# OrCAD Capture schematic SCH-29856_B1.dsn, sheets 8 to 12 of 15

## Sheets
8 08 AUDIO: size C
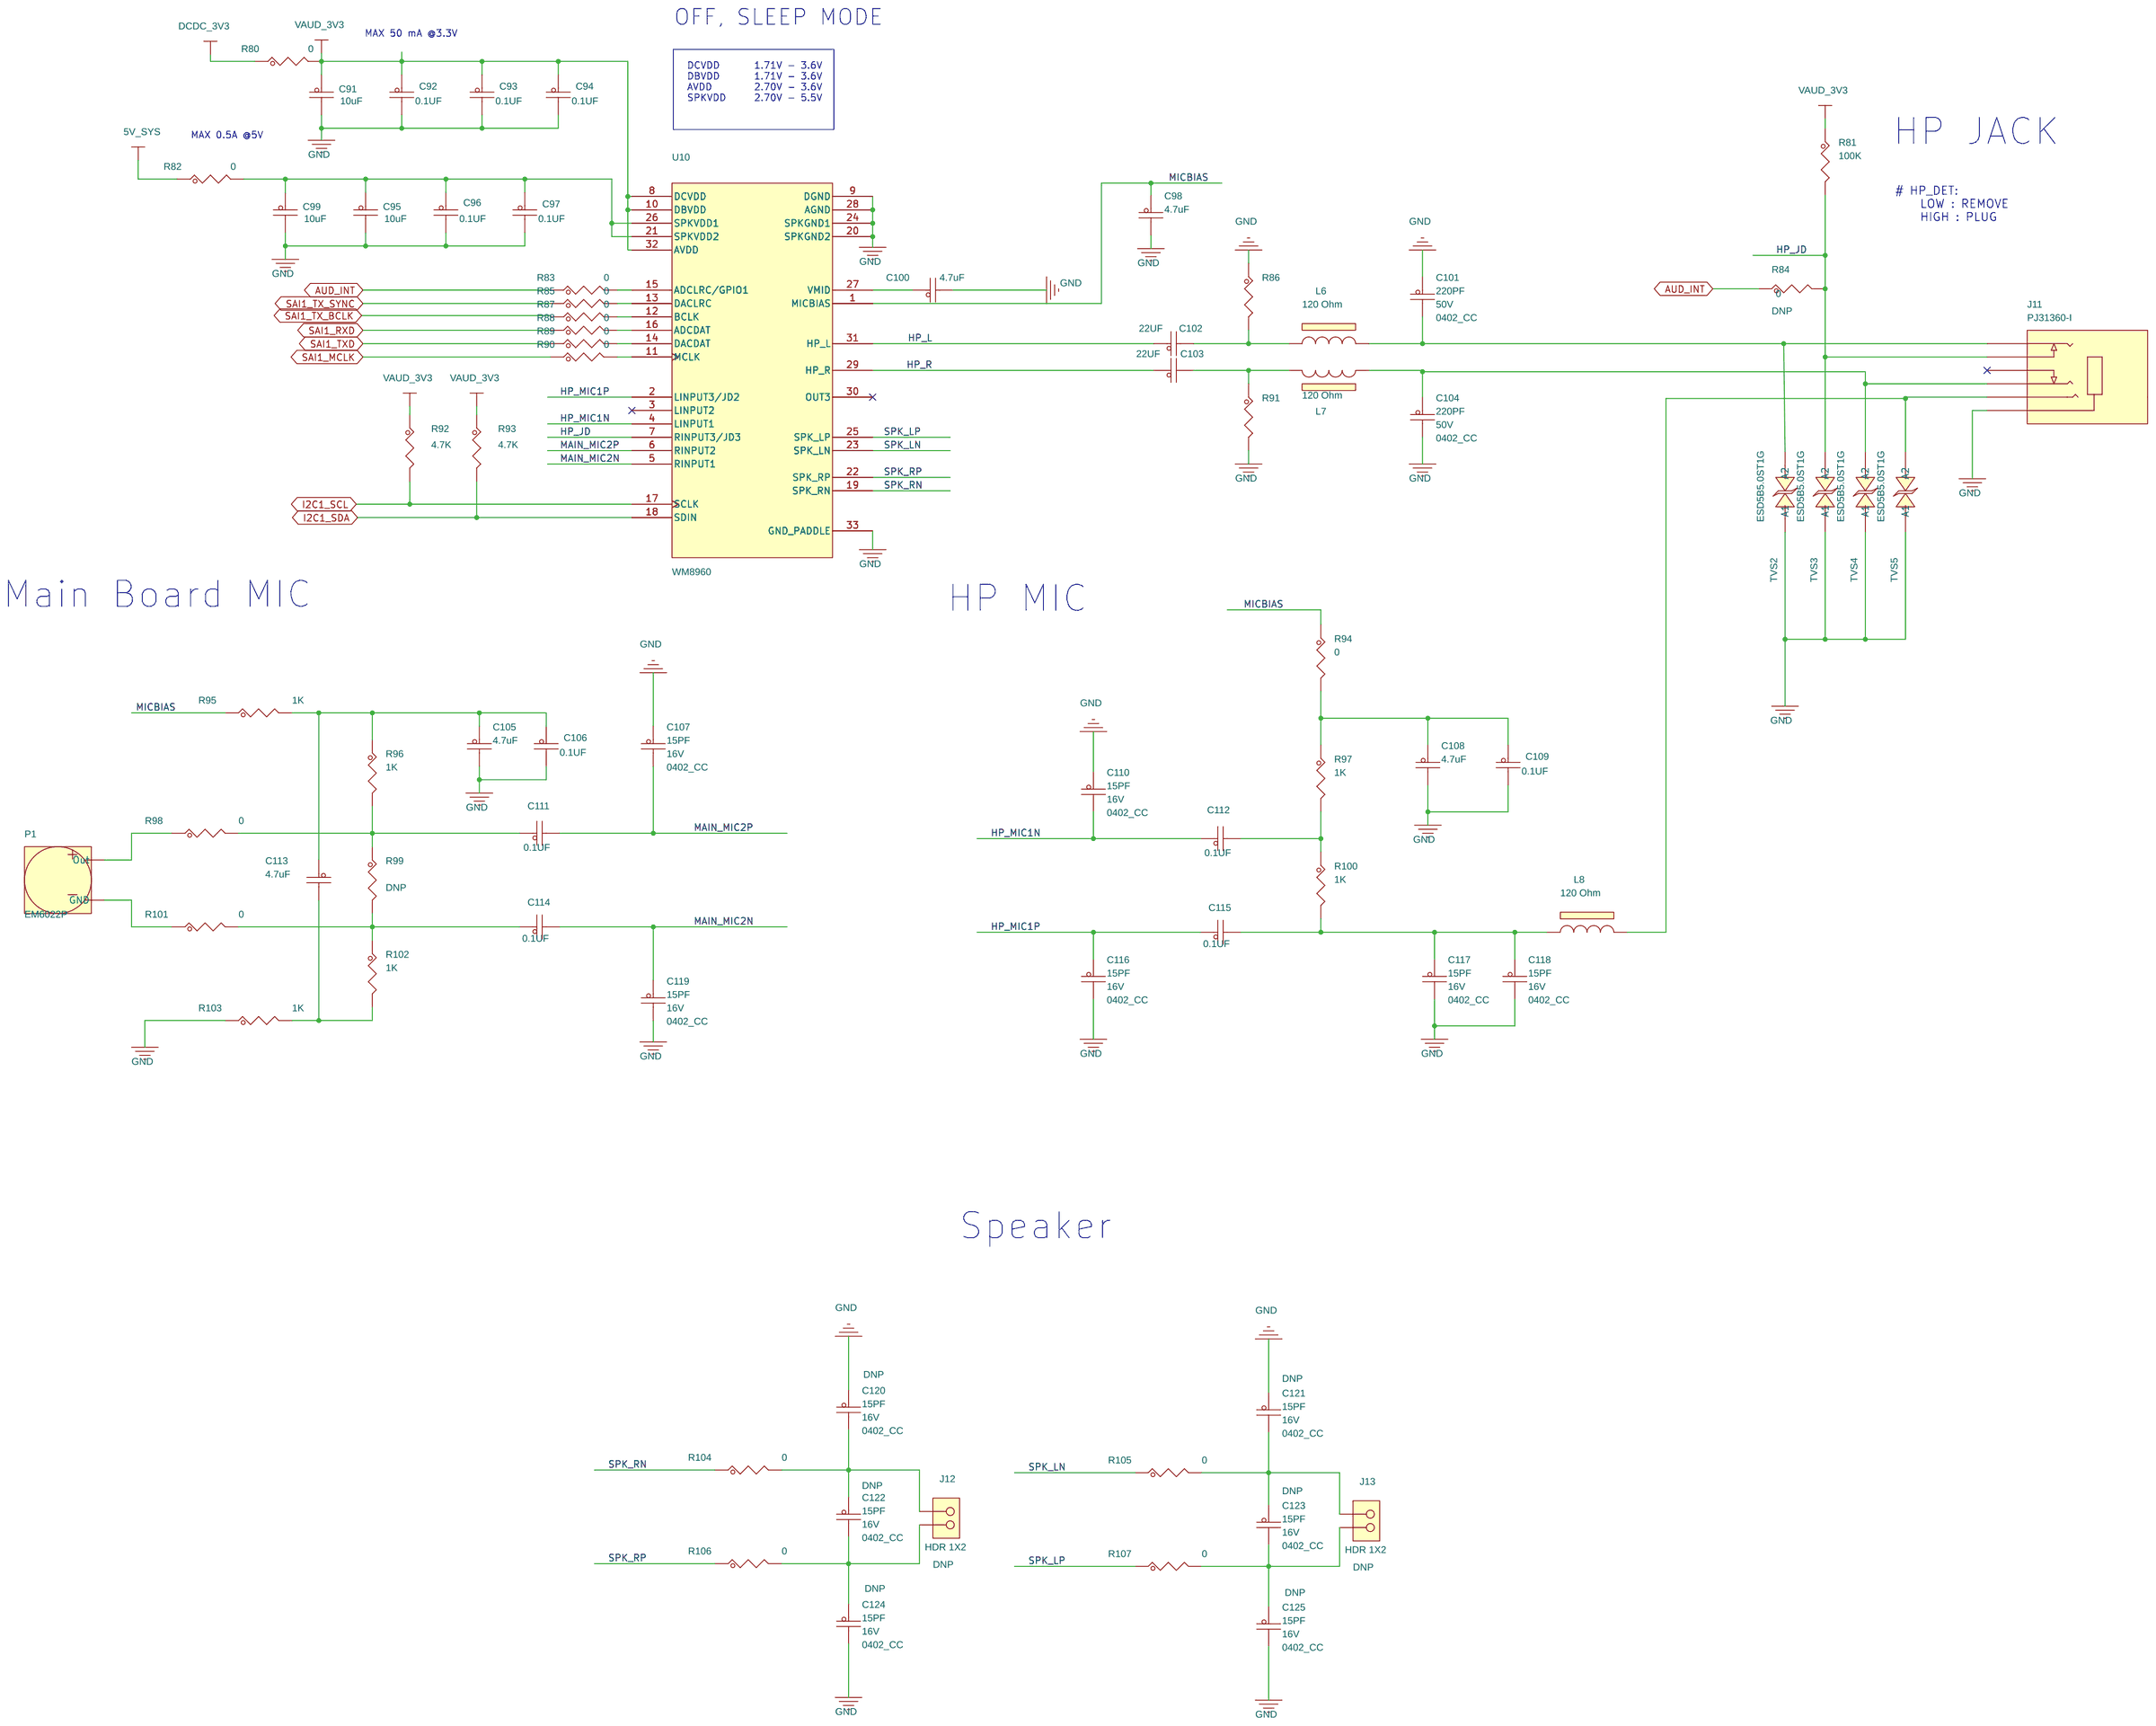
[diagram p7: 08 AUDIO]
9 09 ETHERNET: size C
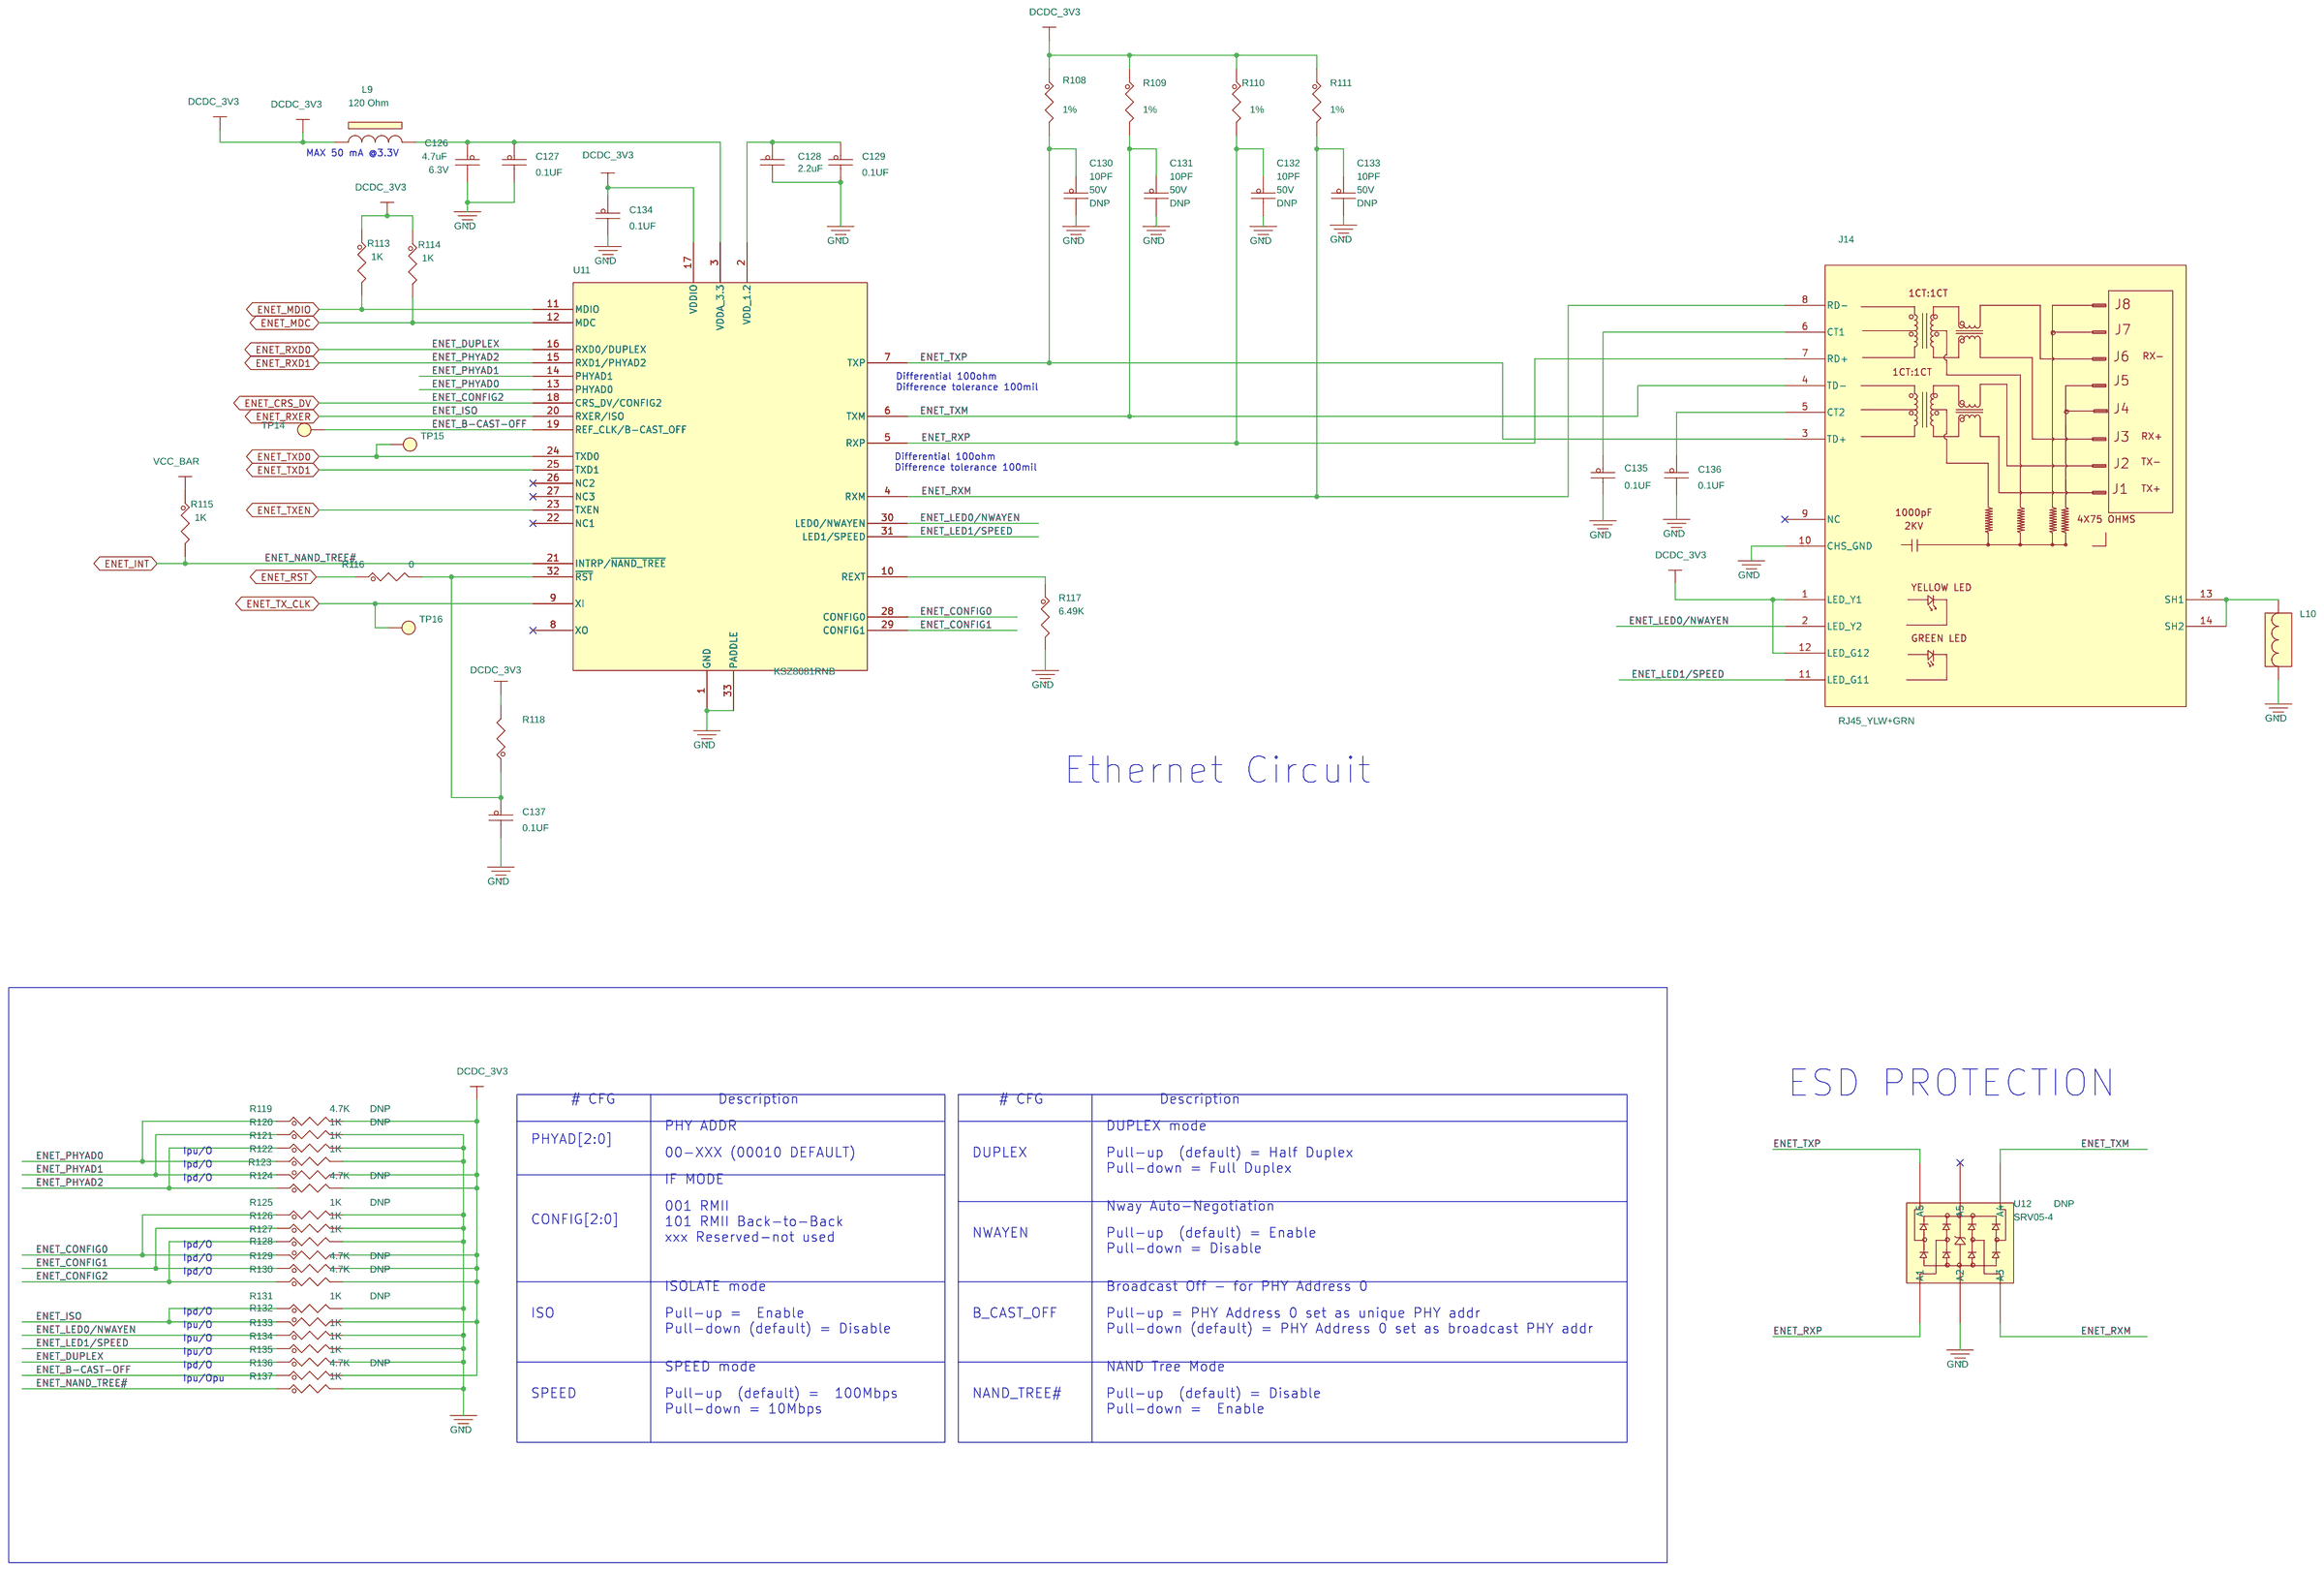
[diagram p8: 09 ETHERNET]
10 12 SDRAM: size C
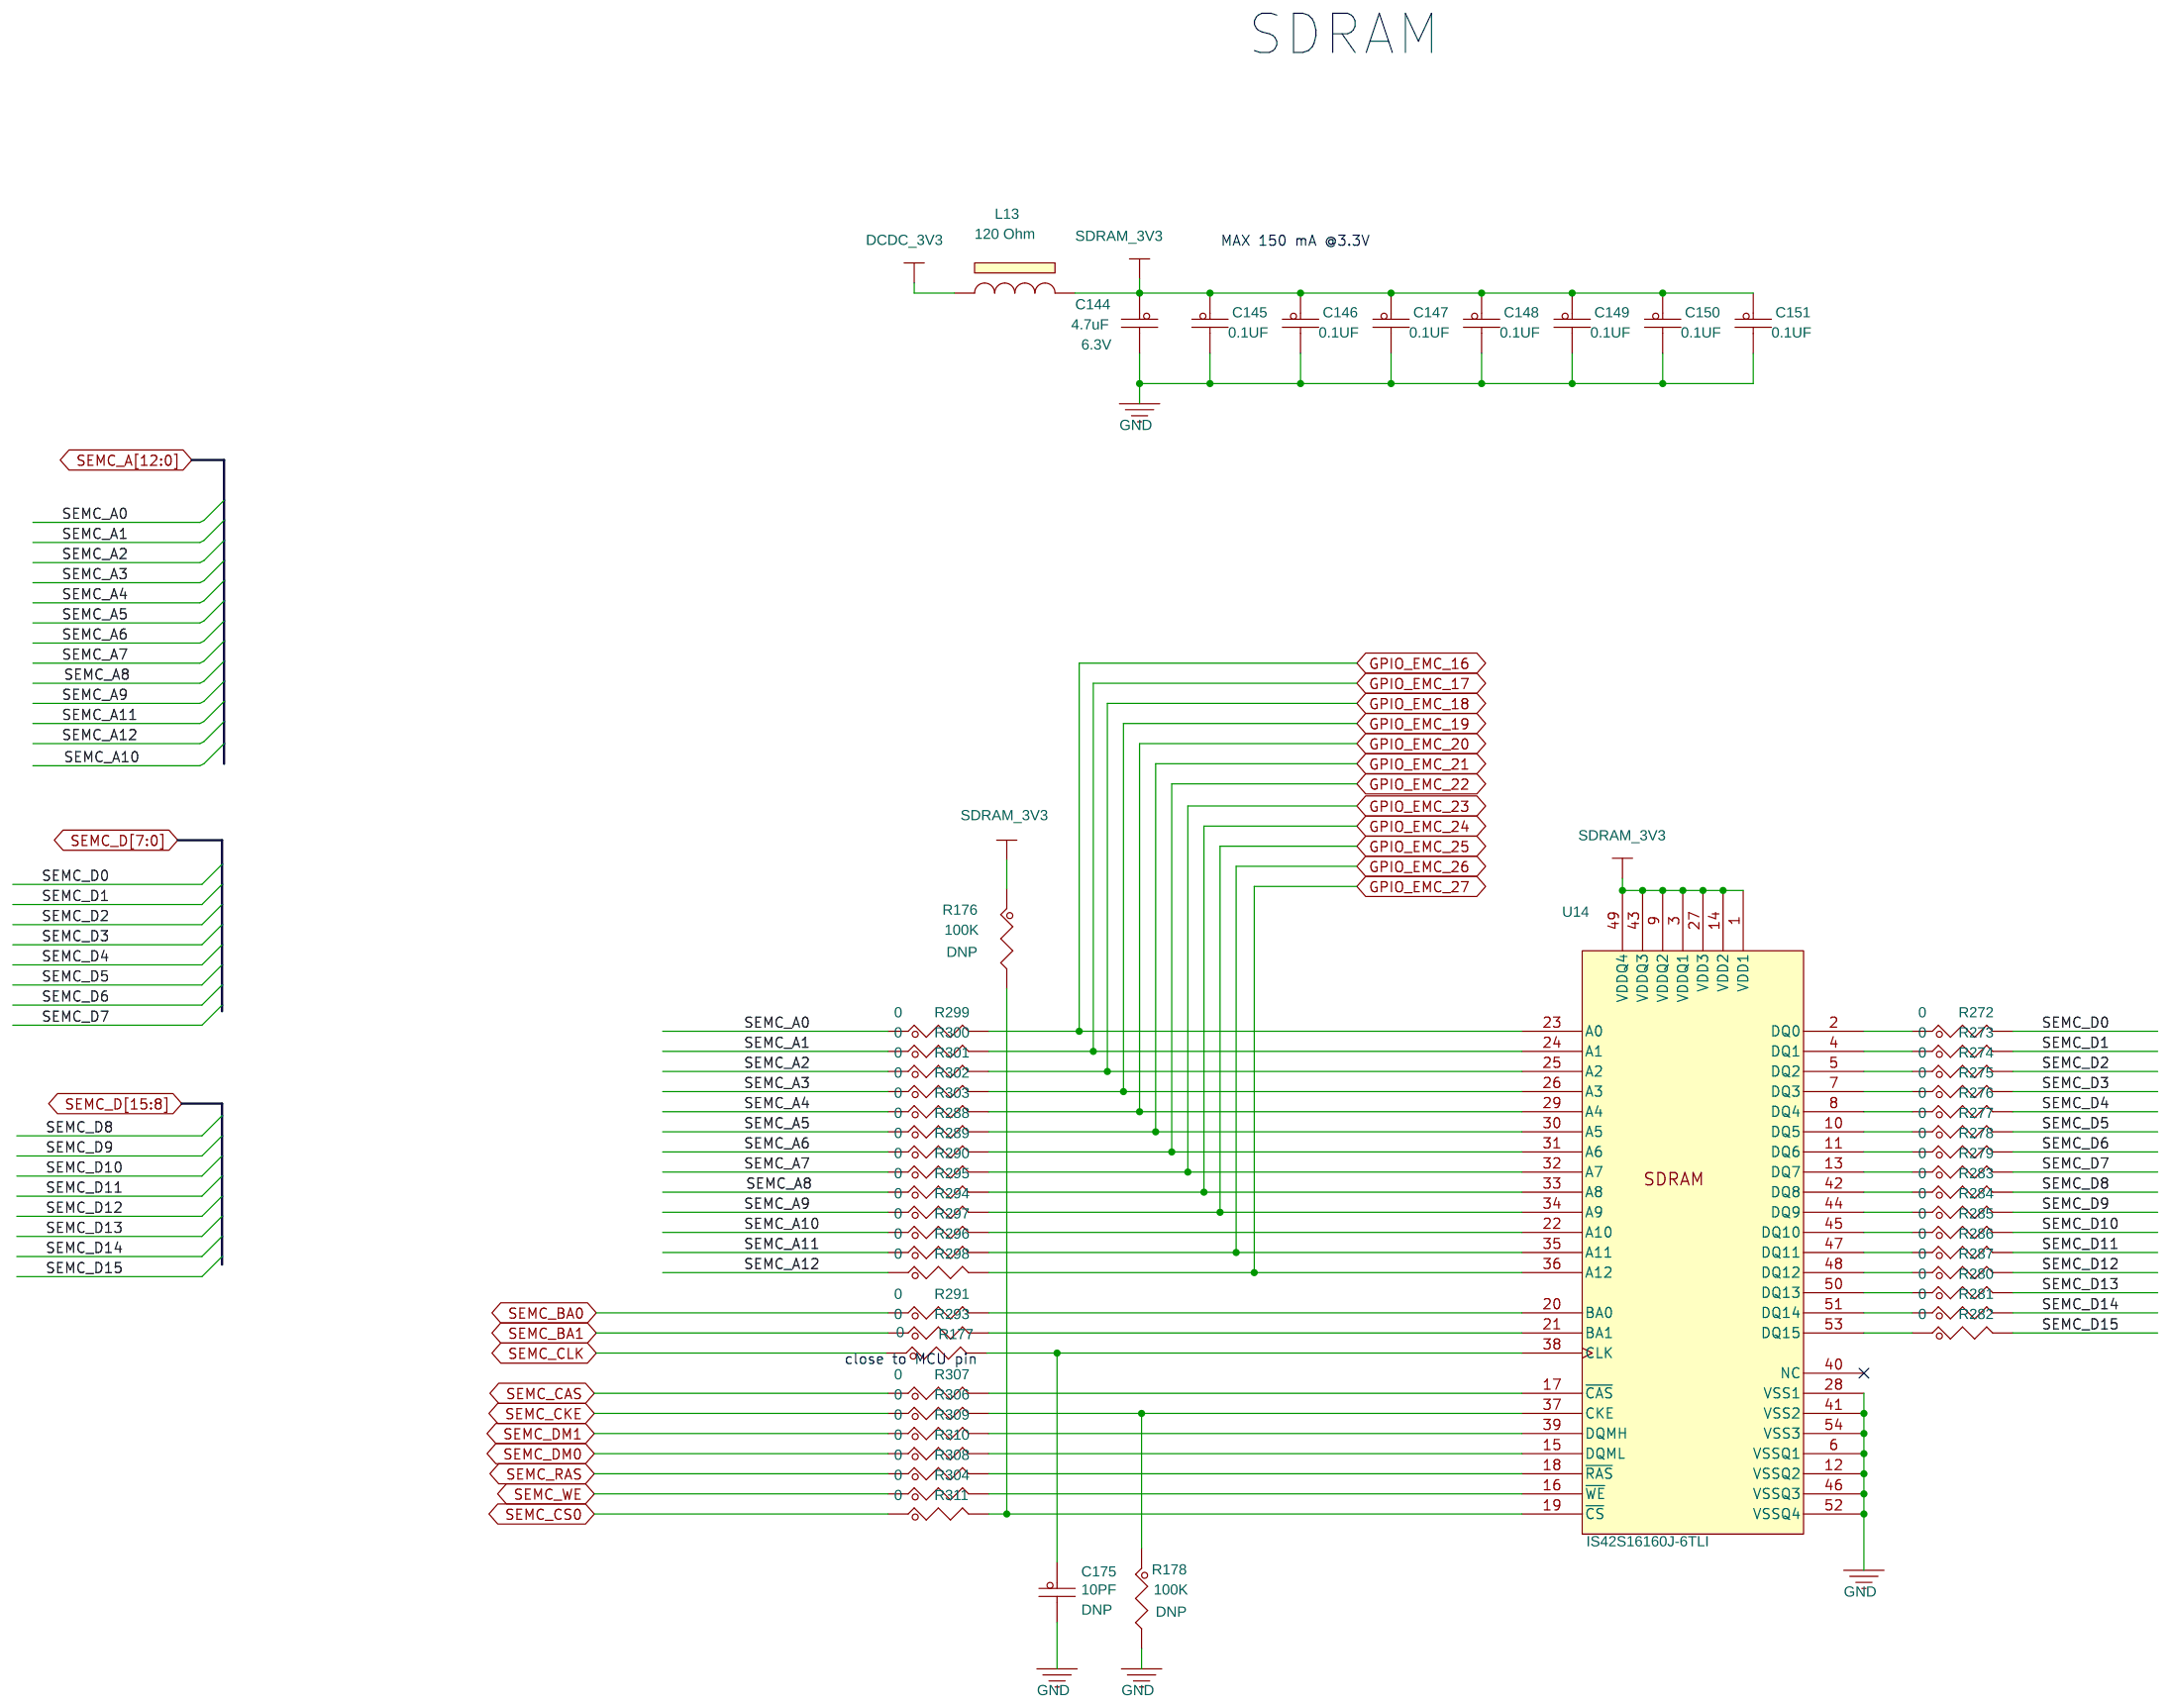
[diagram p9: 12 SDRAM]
11 13 FREELINK: size D
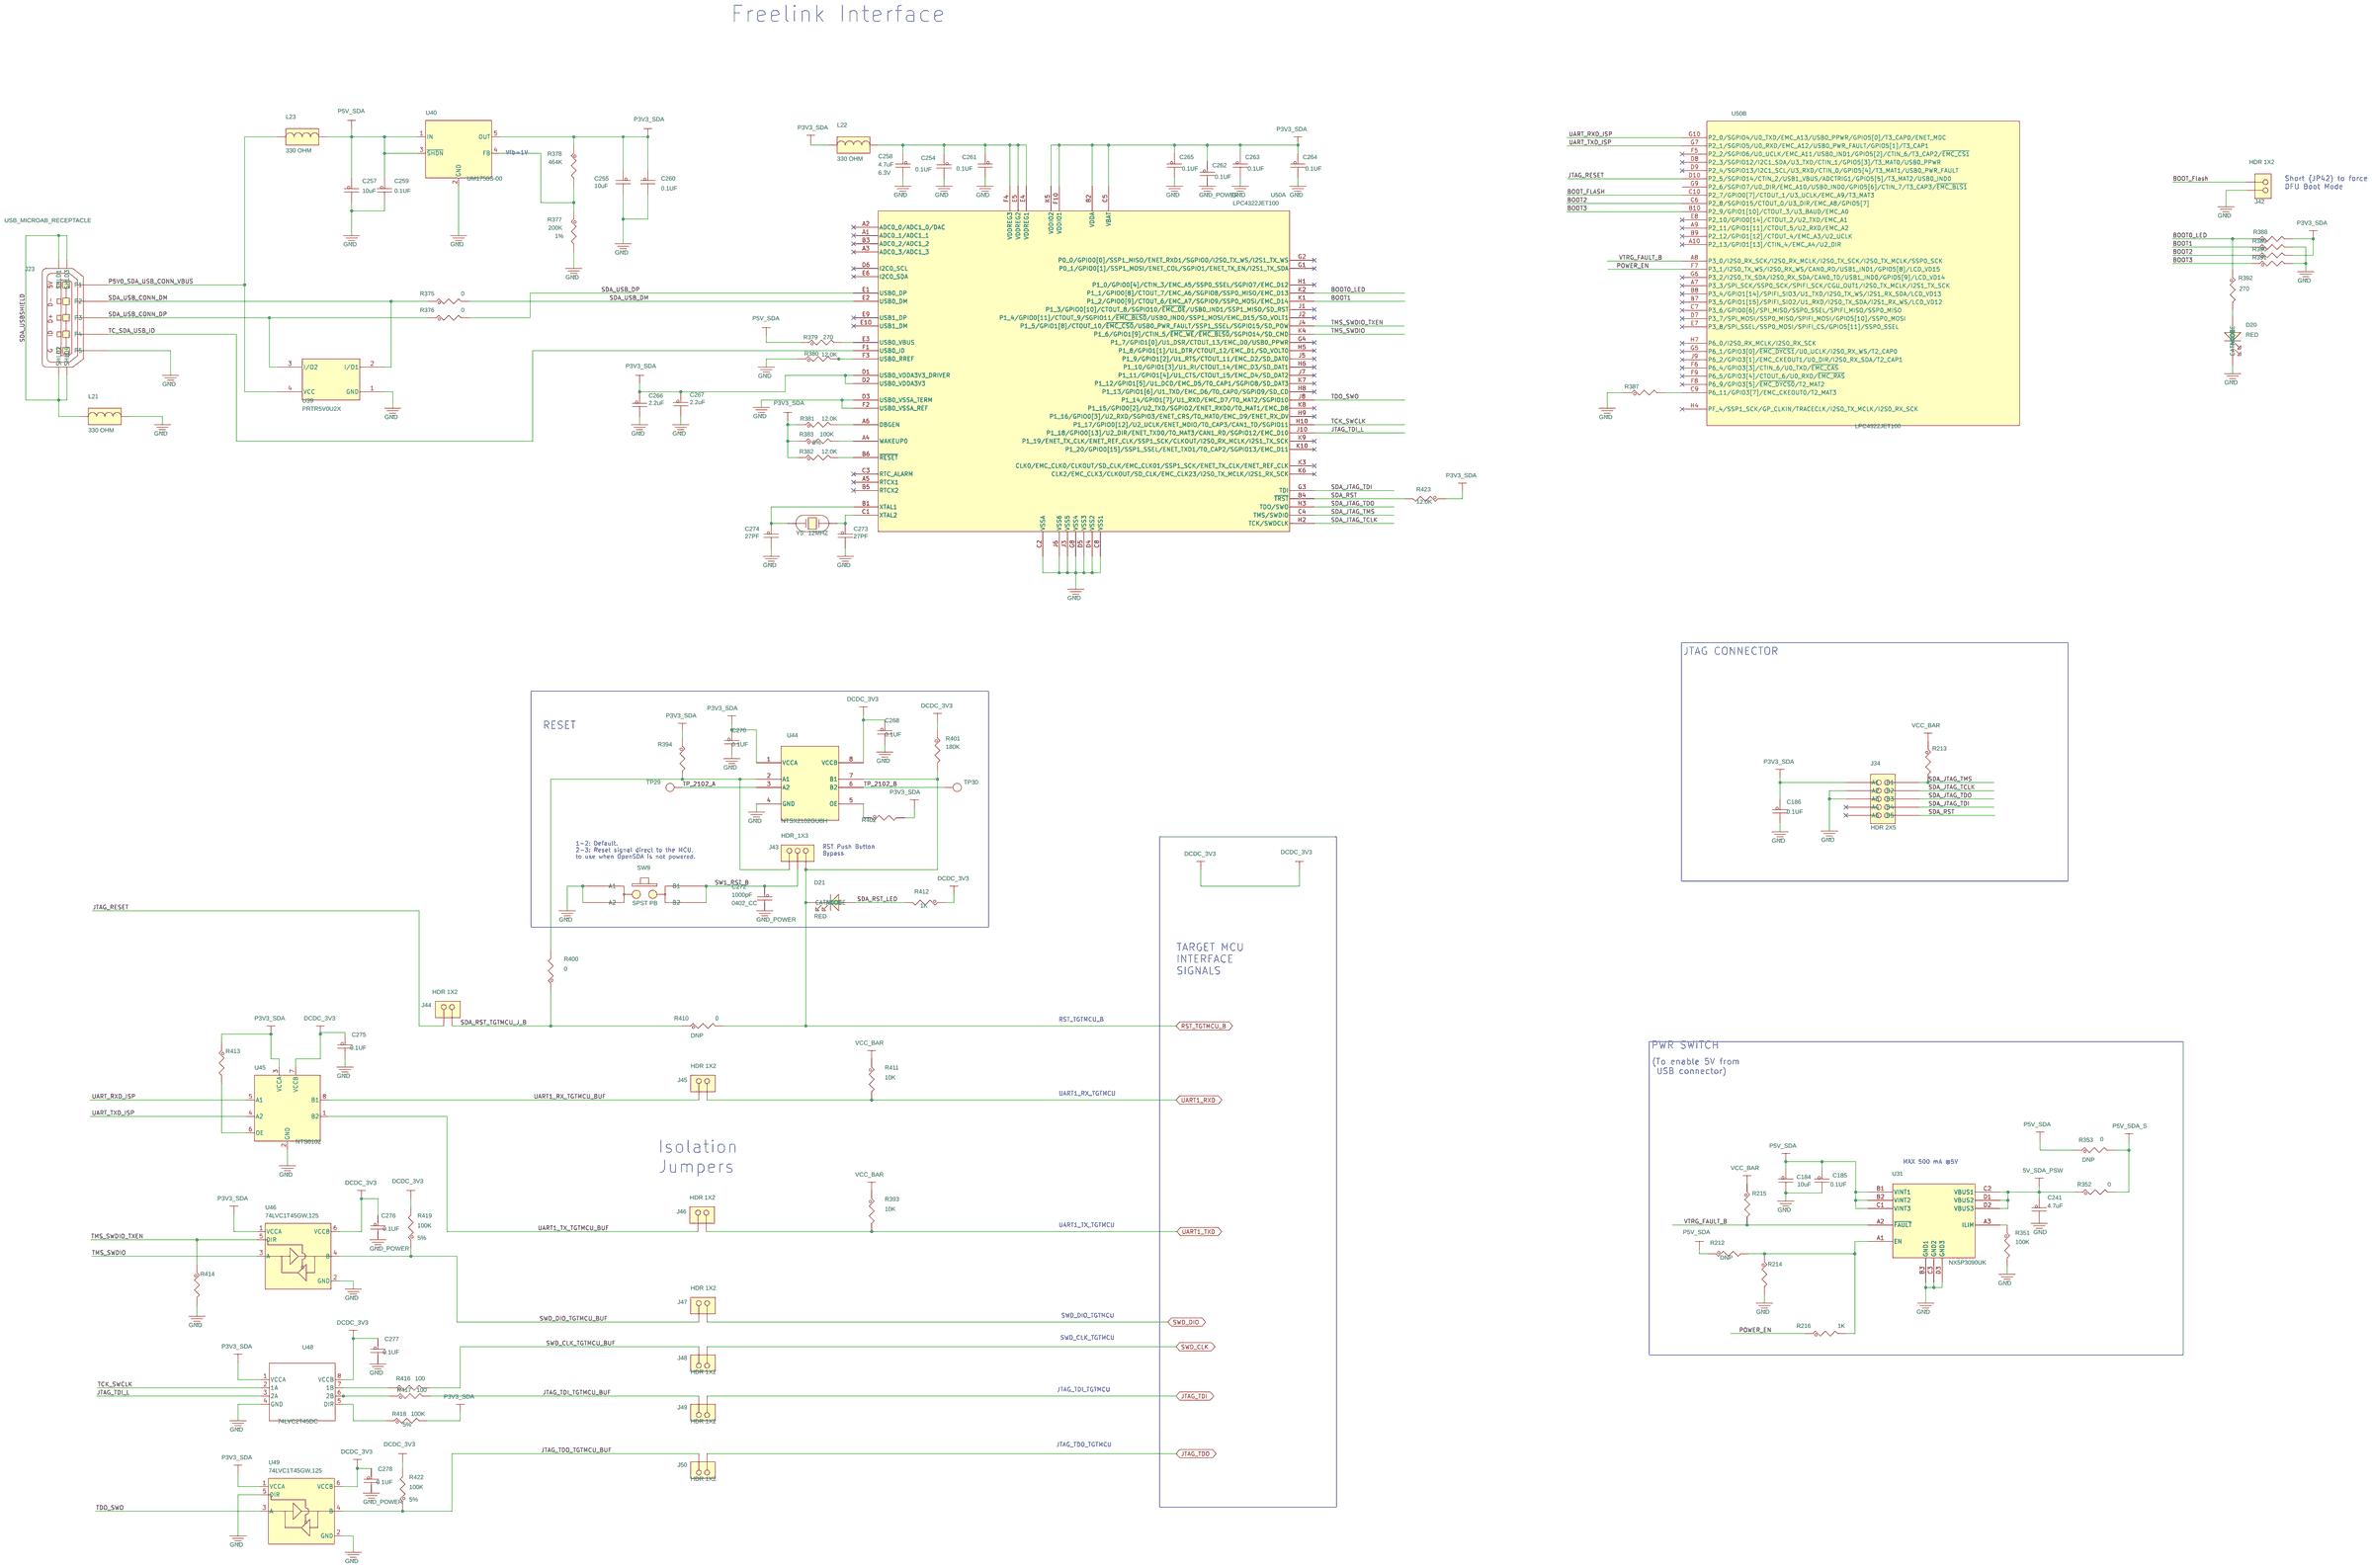
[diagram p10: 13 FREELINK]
12 14 BOOT: size C
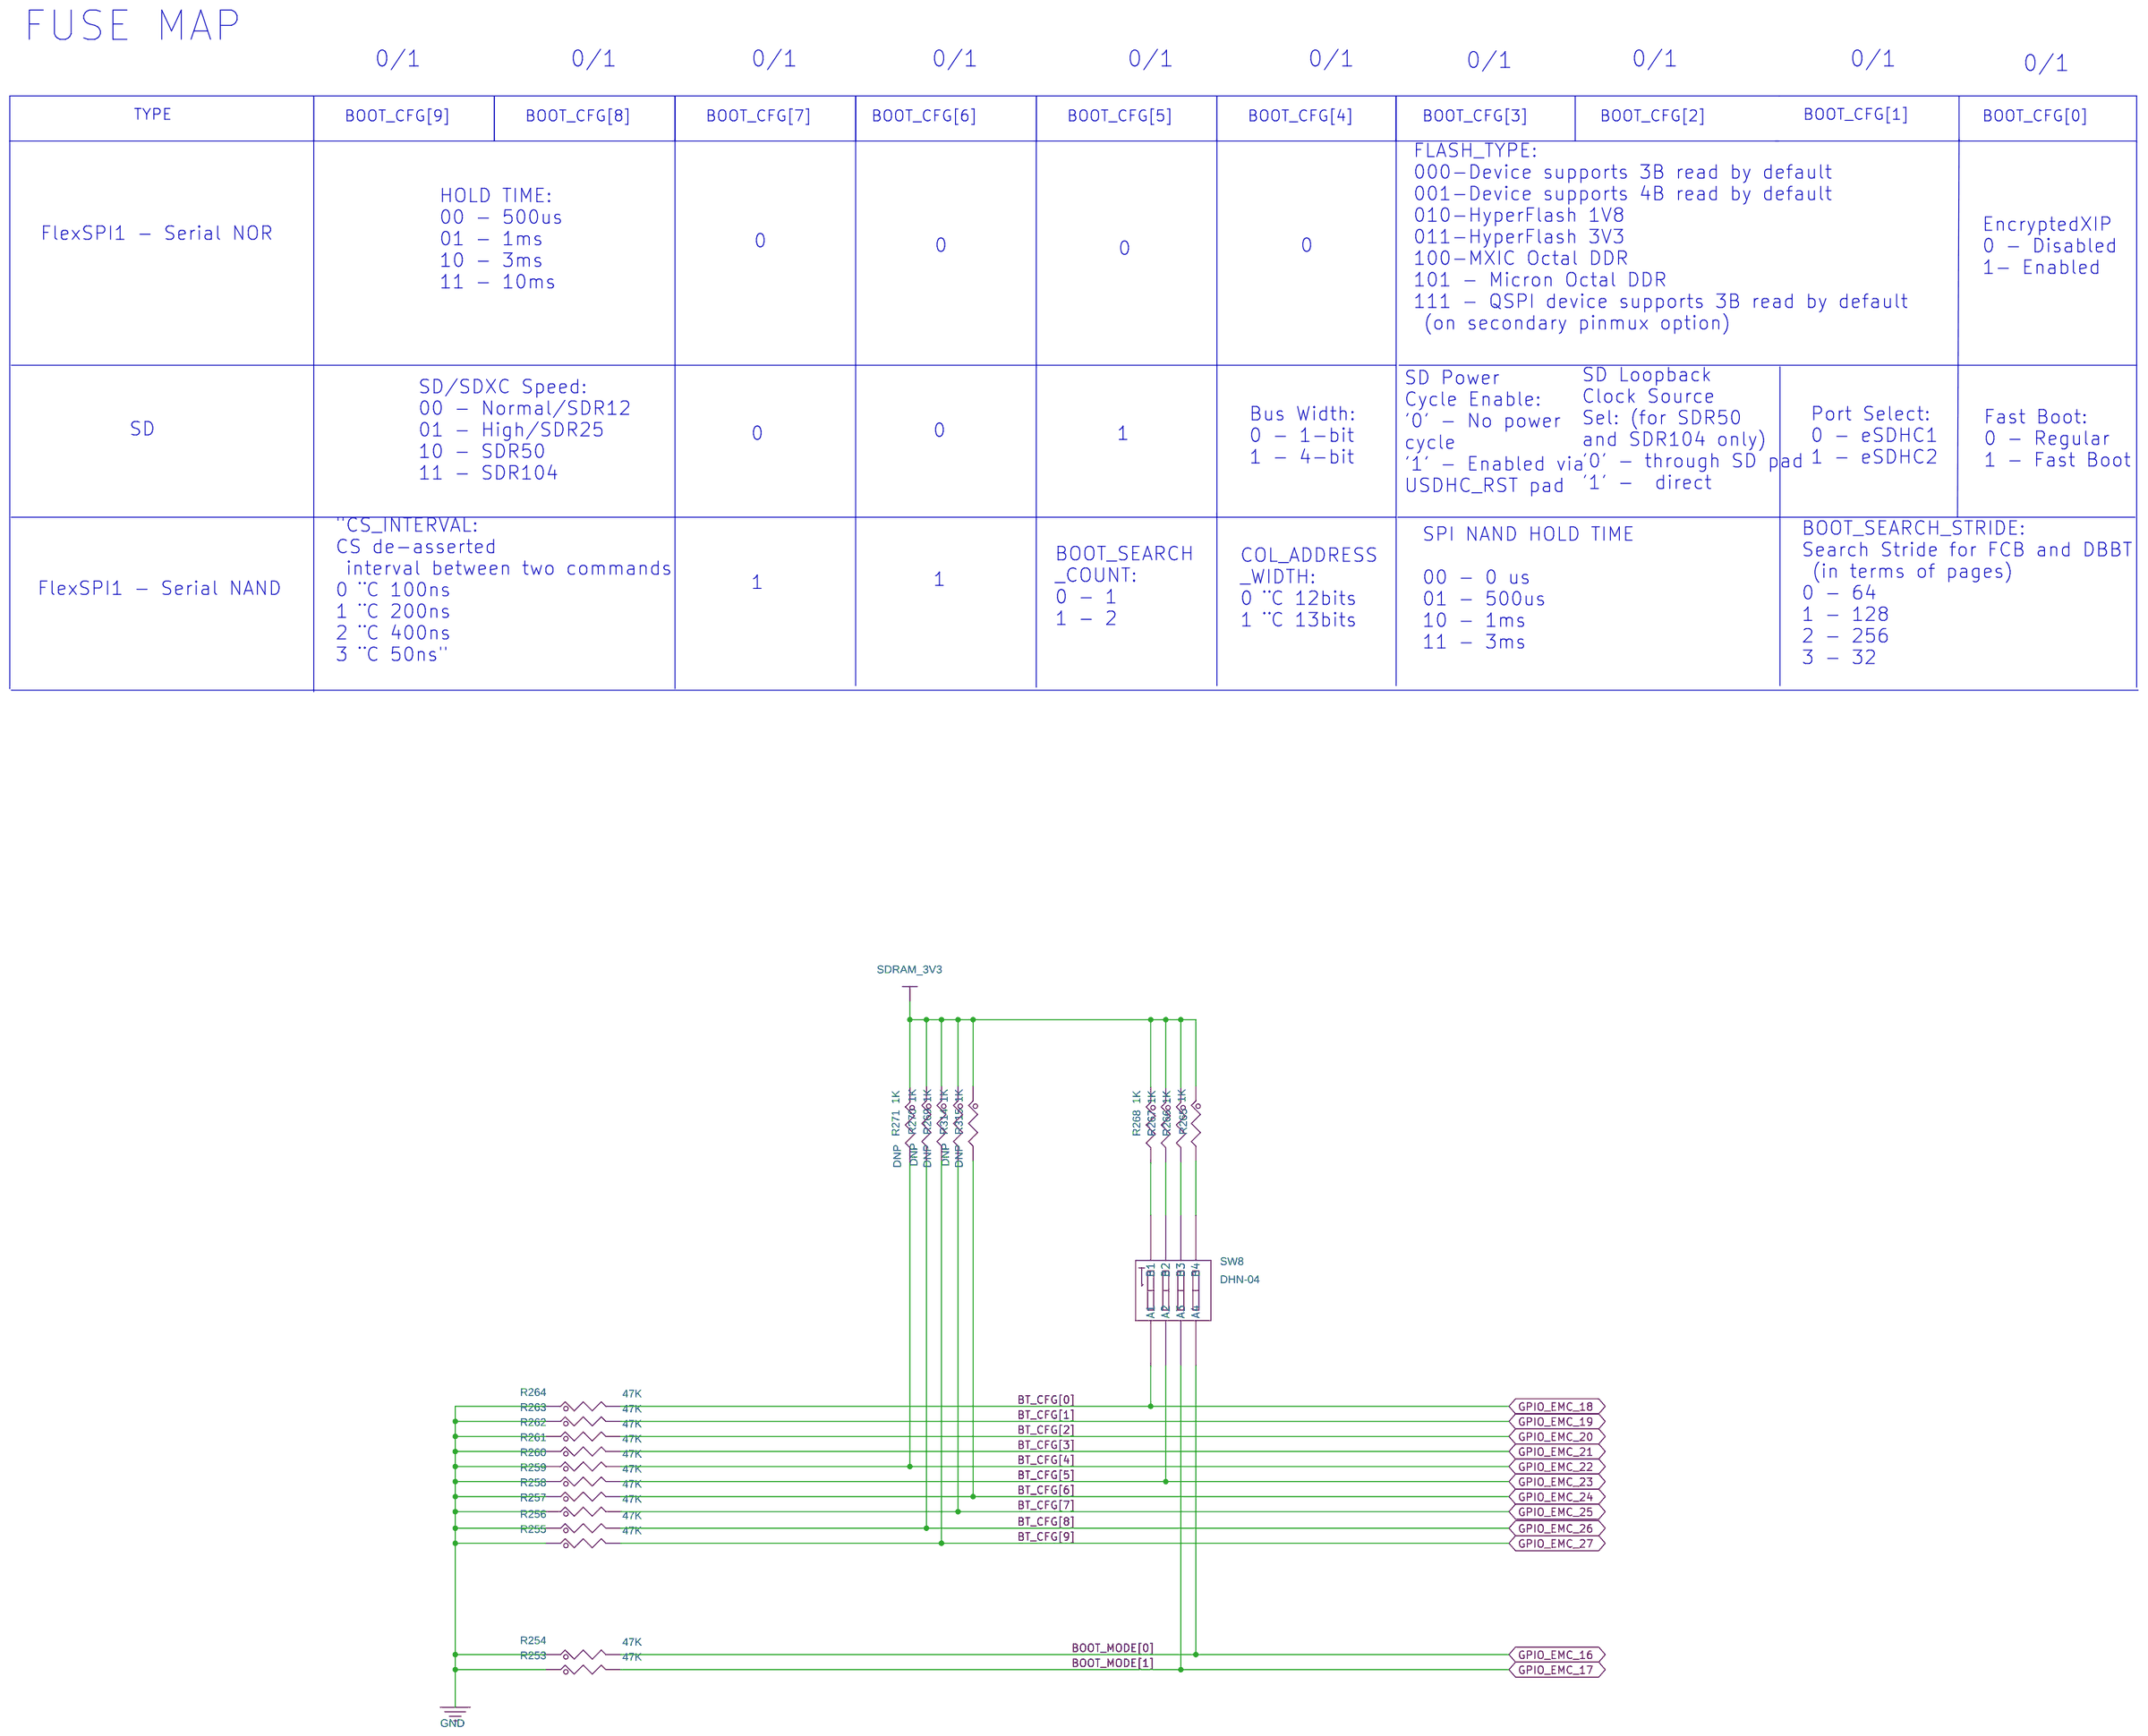
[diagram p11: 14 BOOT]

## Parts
sheet 08 AUDIO
C91  10uF  [CC0603_OV]
C92  0.1UF  [CC0402_25]
C93  0.1UF  [CC0402_25]
C94  0.1UF  [CC0402_25]
C95  10uF  [CC0603_OV]
C96  0.1UF  [CC0402_25]
C97  0.1UF  [CC0402_25]
C98  4.7uF  [0402_CC]
C99  10uF  [CC0603_OV]
C100  4.7uF  [0402_CC]
C101  220PF  [0402_CC]
C102  22UF  [CC0603_OV]
C103  22UF  [CC0603_OV]
C104  220PF  [0402_CC]
C105  4.7uF  [0402_CC]
C106  0.1UF  [CC0402_25]
C107  15PF  [0402_CC]
C108  4.7uF  [0402_CC]
C109  0.1UF  [CC0402_25]
C110  15PF  [0402_CC]
C111  0.1UF  [CC0402_25]
C112  0.1UF  [CC0402_25]
C113  4.7uF  [0402_CC]
C114  0.1UF  [CC0402_25]
C115  0.1UF  [CC0402_25]
C116  15PF  [0402_CC]
C117  15PF  [0402_CC]
C118  15PF  [0402_CC]
C119  15PF  [0402_CC]
C120  15PF  [0402_CC]
C121  15PF  [0402_CC]
C122  15PF  [0402_CC]
C123  15PF  [0402_CC]
C124  15PF  [0402_CC]
C125  15PF  [0402_CC]
J11  PJ31360-I  [con6_audjack_ra_th]
J12  HDR 1X2  [HDR102]
J13  HDR 1X2  [HDR102]
L6  120 Ohm  [0402_CC]
L7  120 Ohm  [0402_CC]
L8  120 Ohm  [0402_CC]
P1  EM6022P  [mic_WM-63PR]
R80  0  [0402_CC]
R81  100K  [0402_CC]
R82  0  [0402_CC]
R83  0  [0402_CC]
R84  0  [0402_CC]
R85  0  [0402_CC]
R86  10K  [0402_CC]
R87  0  [0402_CC]
R88  0  [0402_CC]
R89  0  [0402_CC]
R90  0  [0402_CC]
R91  10K  [0402_CC]
R92  4.7K  [RC0402_25]
R93  4.7K  [RC0402_25]
R94  0  [0402_CC]
R95  1K  [0402_CC]
R96  1K  [0402_CC]
R97  1K  [0402_CC]
R98  0  [0402_CC]
R99  10K  [0402_CC]
R100  1K  [0402_CC]
R101  0  [0402_CC]
R102  1K  [0402_CC]
R103  1K  [0402_CC]
R104  0  [0402_CC]
R105  0  [0402_CC]
R106  0  [0402_CC]
R107  0  [0402_CC]
TVS2  ESD5B5.0ST1G  [diode2_sod523]
TVS3  ESD5B5.0ST1G  [diode2_sod523]
TVS4  ESD5B5.0ST1G  [diode2_sod523]
TVS5  ESD5B5.0ST1G  [diode2_sod523]
U10  WM8960  [qfn32_s142ep]
sheet 09 ETHERNET
C126  4.7uF  [0402_CC]
C127  0.1UF  [CC0402_25]
C128  2.2uF  [CC0402_25]
C129  0.1UF  [CC0402_25]
C130  10PF  [CC0402_25]
C131  10PF  [CC0402_25]
C132  10PF  [CC0402_25]
C133  10PF  [CC0402_25]
C134  0.1UF  [CC0402_25]
C135  0.1UF  [CC0402_25]
C136  0.1UF  [CC0402_25]
C137  0.1UF  [CC0402_25]
J14  RJ45_YLW+GRN  [con12_rj45_1p02_sm]
L9  120 Ohm  [0402_CC]
L10  330 OHM  [ind_1608]
R108  49.9  [RC0603_OV]
R109  49.9  [RC0603_OV]
R110  49.9  [RC0603_OV]
R111  49.9  [RC0603_OV]
R113  1K  [0402_CC]
R114  1K  [0402_CC]
R115  1K  [0402_CC]
R116  0  [0402_CC]
R117  6.49K  [0402_CC]
R118  10K  [0402_CC]
R119  4.7K  [0402_CC]
R120  1K  [0402_CC]
R121  1K  [0402_CC]
R122  1K  [0402_CC]
R123  4.7K  [RC0402_25]
R124  4.7K  [0402_CC]
R125  1K  [0402_CC]
R126  1K  [0402_CC]
R127  1K  [0402_CC]
R128  4.7K  [RC0402_25]
R129  4.7K  [0402_CC]
R130  4.7K  [0402_CC]
R131  1K  [0402_CC]
R132  4.7K  [RC0402_25]
R133  1K  [0402_CC]
R134  1K  [0402_CC]
R135  1K  [0402_CC]
R136  4.7K  [0402_CC]
R137  1K  [0402_CC]
TP14  TP_35MIL  [testpoint_35mil]
TP15  TP_35MIL  [testpoint_35mil]
TP16  TP_35MIL  [testpoint_35mil]
U11  KSZ8081RNB  [qfn32_0p5_ep3p3]
U12  SRV05-4  [SOT23_S6]
sheet 12 SDRAM
C144  4.7uF  [0402_CC]
C145  0.1UF  [CC0402_25]
C146  0.1UF  [CC0402_25]
C147  0.1UF  [CC0402_25]
C148  0.1UF  [CC0402_25]
C149  0.1UF  [CC0402_25]
C150  0.1UF  [CC0402_25]
C151  0.1UF  [CC0402_25]
C175  10PF  [CC0402_25]
L13  120 Ohm  [0402_CC]
R176  100K  [0402_CC]
R177  0  [0402_CC]
R178  100K  [0402_CC]
R272  0  [0402_CC]
R273  0  [0402_CC]
R274  0  [0402_CC]
R275  0  [0402_CC]
R276  0  [0402_CC]
R277  0  [0402_CC]
R278  0  [0402_CC]
R279  0  [0402_CC]
R280  0  [0402_CC]
R281  0  [0402_CC]
R282  0  [0402_CC]
R283  0  [0402_CC]
R284  0  [0402_CC]
R285  0  [0402_CC]
R286  0  [0402_CC]
R287  0  [0402_CC]
R288  0  [0402_CC]
R289  0  [0402_CC]
R290  0  [0402_CC]
R291  0  [0402_CC]
R293  0  [0402_CC]
R294  0  [0402_CC]
R295  0  [0402_CC]
R296  0  [0402_CC]
R297  0  [0402_CC]
R298  0  [0402_CC]
R299  0  [0402_CC]
R300  0  [0402_CC]
R301  0  [0402_CC]
R302  0  [0402_CC]
R303  0  [0402_CC]
R304  0  [0402_CC]
R306  0  [0402_CC]
R307  0  [0402_CC]
R308  0  [0402_CC]
R309  0  [0402_CC]
R310  0  [0402_CC]
R311  0  [0402_CC]
U14  IS42S16160J-6TLI  [tsopii_54]
sheet 13 FREELINK
C184  10uF  [CC0603_OV]
C185  0.1UF  [CC0402_25]
C186  0.1UF  [CC0402_25]
C241  4.7uF  [0402_CC]
C254  0.1UF  [CC0402_25]
C255  10uF  [CC0603_OV]
C257  10uF  [CC0603_OV]
C258  4.7uF  [0402_CC]
C259  0.1UF  [CC0402_25]
C260  0.1UF  [CC0402_25]
C261  0.1UF  [CC0402_25]
C262  0.1UF  [CC0402_25]
C263  0.1UF  [CC0402_25]
C264  0.1UF  [CC0402_25]
C265  0.1UF  [CC0402_25]
C266  2.2uF  [CC0402_25]
C267  2.2uF  [CC0402_25]
C268  0.1UF  [CC0402_25]
C270  0.1UF  [CC0402_25]
C272  1000pF  [0402_CC]
C273  27PF  [CC0402_25]
C274  27PF  [CC0402_25]
C275  0.1UF  [CC0402_25]
C276  0.1UF  [CC0402_25]
C277  0.1UF  [CC0402_25]
C278  0.1UF  [CC0402_25]
D20  RED  [LED_0603]
D21  RED  [LED_0603]
J23  USB_MICROAB_RECEPTACLE  [con_usb5_microab_0p65_sm]
J34  HDR 2X5  [hdr205_50_th]
J42  HDR 1X2  [HDR102]
J43  HDR_1X3  [HDR103]
J44  HDR 1X2  [HDR102]
J45  HDR 1X2  [HDR102]
J46  HDR 1X2  [HDR102]
J47  HDR 1X2  [HDR102]
J48  HDR 1X2  [HDR102]
J49  HDR 1X2  [HDR102]
J50  HDR 1X2  [HDR102]
L21  330 OHM  [ind_1608]
L22  330 OHM  [ind_1608]
L23  330 OHM  [ind_1608]
R212  10K  [0402_CC]
R213  10K  [0402_CC]
R214  15K  [RC0402_25]
R215  10K  [0402_CC]
R216  1K  [0402_CC]
R351  100K  [RC0402_25]
R352  0  [0402_CC]
R353  0  [0402_CC]
R375  0  [0402_CC]
R376  0  [0402_CC]
R377  200K  [0402_CC]
R378  464K  [0402_CC]
R379  270  [RC0402_25]
R380  12.0K  [RC0402_25]
R381  12.0K  [RC0402_25]
R382  12.0K  [RC0402_25]
R383  100K  [0402_CC]
R387  2.2K  [RC0402_25]
R388  2.2K  [RC0402_25]
R389  2.2K  [RC0402_25]
R390  2.2K  [RC0402_25]
R391  2.2K  [RC0402_25]
R392  270  [RC0402_25]
R393  10K  [0402_CC]
R394  10K  [0402_CC]
R400  0  [0402_CC]
R401  180K  [RC0402_25]
R402  4.7K  [RC0402_25]
R410  0  [0402_CC]
R411  10K  [0402_CC]
R412  1K  [0402_CC]
R413  4.7K  [RC0402_25]
R414  2.2K  [RC0402_25]
R416  100  [RC0402_25]
R417  100  [RC0402_25]
R418  100K  [0402_CC]
R419  100K  [0402_CC]
R422  100K  [0402_CC]
R423  12.0K  [RC0402_25]
SW9  SPST PB  [SW4_PB_ESW_SM_P177]
TP29  TPAD_030  [TPAD_030]
TP30  TPAD_030  [TPAD_030]
U31  NX5P3090UK  [wlcsp12_0p4_1p38x1p68mm_smdp]
U39  PRTR5V0U2X  [SOT143B]
U40  UM1750S-00  [sot23-5_a]
U44  NTSX2102GU8H  [xqfn8_1p45x1p25mm]
U45  NTS0102  [tssop8_a]
U46  74LVC1T45GW,125  [SOT-363_0P65_SMT]
U48  74LVC2T45DC  [SSOP8_DCU]
U49  74LVC1T45GW,125  [SOT-363_0P65_SMT]
U50  LPC4322JET100  [fbga100_0p8_9x9]  (sections A,B)
Y5  12MHZ  [xtl2_11p6x4p85_sm]
sheet 14 BOOT
R253  47K  [RC0402_25]
R254  47K  [RC0402_25]
R255  47K  [RC0402_25]
R256  47K  [RC0402_25]
R257  47K  [RC0402_25]
R258  47K  [RC0402_25]
R259  47K  [RC0402_25]
R260  47K  [RC0402_25]
R261  47K  [RC0402_25]
R262  47K  [RC0402_25]
R263  47K  [RC0402_25]
R264  47K  [RC0402_25]
R265  1K  [RC0402_25]
R266  1K  [RC0402_25]
R267  1K  [RC0402_25]
R268  1K  [RC0402_25]
R269  1K  [RC0402_25]
R270  1K  [RC0402_25]
R271  1K  [RC0402_25]
R314  1K  [RC0402_25]
R315  1K  [RC0402_25]
SW8  DHN-04  [97C04]

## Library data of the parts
C91 C95 C99 C184 C255 C257 = CAP_NP: CAP CER 10UF 10V 10% X5R 0603; AGILE_PN: 150-78675; CAD_APPROVED: Yes; FPLIST: CC0603_OV,CC0603,0603_CC; HEIGHT: 1.016MM; MFG_NAME01: MURATA; MFG_PN01: GRM188R61A106KE69D; ROHS: Yes; Temp_Range: -55°C ~ 85°C; Tolerance: 10%; VOLTAGE: 10v
C92-C94 C96 C97 C106 C109 C111 C112 C114 C115 C127 C129 C134-C137 C145-C151 C185 C186 C254 C259-C265 C268 C270 C275-C278 = CAP_NP: CAP CER 0.1UF 10V 10% X5R 0402; AGILE_PN: 150-75634; CAD_APPROVED: Yes; FPLIST: CC0402_25,CC0402_HD,0402_CC; HEIGHT: 0.64MM; MFG_NAME01: KEMET; MFG_PN01: C0402C104K8PAC; ROHS: Yes; Tolerance: 10%; VOLTAGE: 10V
C98 C100 C105 C108 C113 C126 C144 C258 = CAP_NP: CAP CER 4.7UF 6.3V 20% X5R 0402; AGILE_PN: 150-78463; CAD_APPROVED: Yes; FPLIST: CC0402_25,CC0402_HD,0402_CC; HEIGHT: 0.65MM; MFG_NAME01: TDK; MFG_PN01: C1005X5R0J475M050BC; ROHS: Yes; Tolerance: 20%; VOLTAGE: 6.3V; voltage rating: 6.3V
C101 C104 = CAP_NP: CAP CER 220PF 50V 5% C0G 0402; AGILE_PN: 150-30297; CAD_APPROVED: Yes; FPLIST: CC0402_25,CC0402_HD,0402_CC; HEIGHT: 0.55MM; MFG_NAME01: KEMET; MFG_PN01: C0402C221J5GAC; ROHS: Yes; Tolerance: 5%; VOLTAGE: 50V
C102 C103 = CAP_NP: CAP CER 22UF 6.3V 20% X5R 0603; AGILE_PN: 150-78467; CAD_APPROVED: Yes; FPLIST: CC0603_OV,CC0603,0603_CC; HEIGHT: 1MM; MFG_NAME01: Samsung; MFG_PN01: CL10A226MQ8NRNE; ROHS: Yes; Tolerance: 20%; VOLTAGE: 6.3V
C107 C110 C116-C119 = CAP_NP: CAP CER 15PF 16V 5% C0G 0402; AGILE_PN: 150-75720; CAD_APPROVED: Yes; FPLIST: CC0402_25,CC0402_HD,0402_CC; HEIGHT: 0.55MM; MFG_NAME01: KEMET; MFG_PN01: C0402C150J4GAC; ROHS: Yes; Tolerance: 5%; VOLTAGE: 16V
C120-C125 = CAP_NP: CAP CER 15PF 16V 5% C0G 0402; AGILE_PN: 150-75720; ASSY_OPT: DNP; CAD_APPROVED: Yes; FPLIST: CC0402_25,CC0402_HD,0402_CC; HEIGHT: 0.55MM; MFG_NAME01: KEMET; MFG_PN01: C0402C150J4GAC; ROHS: Yes; Tolerance: 5%; VOLTAGE: 16V
J11 = CONN_AUDIOJACK_6P: CON 6 AUD JACK RA SMT -- 191H AU; AGILE_PN: 211-79704; CAD_APPROVED: Yes; HEIGHT: 4.85 MM; MFG_NAME01: SHENZHEN ATOM TECHNOLOGY CO.,LTD; ROHS: Yes
J12 J13 = CONN_HDR_2X1: HDR 1X2 TH 100MIL SP 339H AU 98L; AGILE_PN: 210-81490; ASSY_OPT: DNP; CAD_APPROVED: Yes; HEIGHT: 8.59MM; MFG_NAME01: ANYTRONIC CORPORATION LIMITED; MFG_PN01: 0901S0202011N9T-31RF; ROHS: Yes; Temp_Range: -55°C to +105°C
L6-L9 L13 = INDUCTOR_FERRITE: IND FER BEAD 120 OHM@100MHZ 0.5A 25% 0402; AGILE_PN: 180-77771; CAD_APPROVED: Yes; FPLIST: IND_0402,0402_CC; HEIGHT: 0.55MM; MFG_NAME01: Murata; MFG_PN01: BLM15AG121SN1D; PART_TYPE: FERRITE\BEAD; ROHS: Yes; Tolerance: 25%
P1 = MIC_POM: AUDIO DEVICE MIC 0.5MA 2V 38-48+/-3dB 2.2KOHM 6MM TH; AGILE_PN: 510-77987; CAD_APPROVED: Yes; HEIGHT: 2.4MM; MFG_NAME01: Soberton Inc; ROHS: Yes
R80 R82 R83 R85 R87-R90 R94 R98 R101 R104-R107 R116 R177 R272-R291 R293-R304 R306-R311 R352 R375 R376 R400 = RES: RES MF ZERO OHM 1/16W 5% 0402; AGILE_PN: 470-75394; CAD_APPROVED: Yes; FPLIST: RC0402_25,RC0402_HD,RC0402_X2,0402_CC; HEIGHT: 0.45 MM; MFG_NAME01: ROHM; MFG_PN01: MCR01MZPJ000; ROHS: Yes; Tolerance: 5%
R81 = RES: RES MF 100K 1/16W 5% 0402; AGILE_PN: 470-75597; CAD_APPROVED: Yes; FPLIST: RC0402_25,RC0402_HD,0402_CC; HEIGHT: 0.40 MM; MFG_NAME01: VENKEL COMPANY; MFG_PN01: CR0402-16W-104JT; ROHS: Yes; Temp_Range: -55C to +155C; Tolerance: 5%
R84 R353 R410 = RES: RES MF ZERO OHM 1/16W 5% 0402; AGILE_PN: 470-75394; ASSY_OPT: DNP; CAD_APPROVED: Yes; FPLIST: RC0402_25,RC0402_HD,RC0402_X2,0402_CC; HEIGHT: 0.45 MM; MFG_NAME01: ROHM; MFG_PN01: MCR01MZPJ000; ROHS: Yes; Tolerance: 5%
R86 R91 R393 R411 = RES: RES MF 10K 1/16W 5% 0402; AGILE_PN: 470-75557; CAD_APPROVED: Yes; FPLIST: RC0402_25,RC0402_HD,0402_CC; HEIGHT: 0.4 MM; MFG_NAME01: VISHAY INTERTECHNOLOGY; MFG_PN01: CRCW040210K0JNED; ROHS: Yes; Tolerance: 5%
R92 R93 = RES: RES MF 4.7K 1/16W 5% 0402; AGILE_PN: 470-75626; CAD_APPROVED: Yes; FPLIST: RC0402_25,RC0402_HD,0402_CC; HEIGHT: 0.41mm; MFG_NAME01: NIC COMPONENTS CORP; MFG_PN01: NRCL04J472TRF; ROHS: Yes; Tolerance: 5%
R95-R97 R100 R102 R103 R113-R115 R121 R122 R126 R127 R133-R135 R137 R216 R265-R268 R412 = RES: RES MF 1.0K 1/16W 5% 0402; AGILE_PN: 470-75555; CAD_APPROVED: Yes; FPLIST: RC0402_25,RC0402_HD,RC0402_X2,0402_CC; HEIGHT: 0.41mm; MFG_NAME01: VISHAY INTERTECHNOLOGY; MFG_PN01: CRCW04021K00JNED; ROHS: Yes; Tolerance: 5%
R99 = RES: RES MF 10K 1/16W 5% 0402; AGILE_PN: 470-75557; ASSY_OPT: DNP; CAD_APPROVED: Yes; FPLIST: RC0402_25,RC0402_HD,0402_CC; HEIGHT: 0.4 MM; MFG_NAME01: VISHAY INTERTECHNOLOGY; MFG_PN01: CRCW040210K0JNED; ROHS: Yes; TOL: 5%; Tolerance: 5%
TVS2-TVS5 = DIODE_TVS_BIDIR: DIODE SUPPRESSOR 16A@30NS 5V@1UA SOD-523; AGILE_PN: 480-76937; CAD_APPROVED: Yes; HEIGHT: 0.7MM; MFG_NAME01: on semiconductor; ROHS: Yes
U10 = WM8960_QFN_33P: IC CODEC STEREO WITH CLASS D SPEAKER DRIVER 1.71-3.6V QFN32; AGILE_PN: 315-79450; CAD_APPROVED: Yes; HEIGHT: 1MM; MFG_NAME01: WOLFSON MICROELECTRONICS; MFG_PN01: WM8960CGEFL/RV; ROHS: Yes
C128 C266 C267 = CAP_NP: CAP CER 2.2uF 6.3V 10% X5R 0402; AGILE_PN: 150-79454; CAD_APPROVED: Yes; FPLIST: CC0402_25,CC0402_HD,0402_CC; HEIGHT: 0.55MM; MFG_NAME01: MURATA; MFG_PN01: GRM155R60J225KE95; ROHS: Yes; Tolerance: 10%; VOLTAGE: 6.3V
C130-C133 = CAP_NP: CAP CER 10PF 50V 5% C0G 0402; AGILE_PN: 150-75265; ASSY_OPT: DNP; CAD_APPROVED: YES; FPLIST: CC0402_25,CC0402_HD,0402_CC; HEIGHT: 0.635MM; MFG_NAME01: AVX; MFG_PN01: 04025A100JAT2A; ROHS: Yes; TOL: 5%; Tolerance: 5%; VOLTAGE: 50V
J14 = RJ45_HR961160C_12P: CON 12 RJ45 SHLD RA SM 1.02MM SP 625H --; AGILE_PN: 211-79967; CAD_APPROVED: Yes; HEIGHT: 15.88 MM; MFG_NAME01: HanRun Electronics Co., Ltd; MFG_PN01: HR961160C; ROHS: Yes
L10 = BEAD: IND FER BEAD 330OHM@100MHZ 1.7A 0603; AGILE_PN: 180-78156; CAD_APPROVED: Yes; HEIGHT: 0.95MM; MFG_NAME01: TDK; MFG_PN01: MPZ1608S331A; PART_TYPE: FERRITE\BEAD; ROHS: Yes; TOL: 25%; Tolerance: 25%
R108-R111 = RES: RES MF 49.9 OHM 1/10W 1% 0603; AGILE_PN: 470-75432; CAD_APPROVED: Yes; FPLIST: RC0603_OV,RC0603,0603_CC; HEIGHT: 0.55 MM; MFG_NAME01: BOURNS; MFG_PN01: CR0603-FX-49R9ELF; ROHS: Yes; TOL: 1%; Tolerance: 1%
R117 = RES: RES MF 6.49K  1/16W 1% 0402; AGILE_PN: 470-30927; CAD_APPROVED: Yes; FPLIST: RC0402_25,RC0402_HD,0402_CC; HEIGHT: 0.40 MM; MFG_NAME01: WALSIN TECHNOLOGY CORP.; MFG_PN01: WR04X6491FTL; ROHS: Yes; Tolerance: 1%
R118 R213 R215 R394 = RES: RES MF 10K 1/16W 5% 0402; AGILE_PN: 470-75557; CAD_APPROVED: Yes; FPLIST: RC0402_25,RC0402_HD,0402_CC; HEIGHT: 0.4 MM; MFG_NAME01: VISHAY INTERTECHNOLOGY; MFG_PN01: CRCW040210K0JNED; ROHS: Yes; TOL: 5%; Tolerance: 5%
R119 R124 R129 R130 R136 = RES: RES MF 4.7K 1/16W 5% 0402; AGILE_PN: 470-75626; ASSY_OPT: DNP; CAD_APPROVED: Yes; FPLIST: RC0402_25,RC0402_HD,0402_CC; HEIGHT: 0.41mm; MFG_NAME01: NIC COMPONENTS CORP; MFG_PN01: NRCL04J472TRF; ROHS: Yes; Tolerance: 5%
R120 R125 R131 R269-R271 R314 R315 = RES: RES MF 1.0K 1/16W 5% 0402; AGILE_PN: 470-75555; ASSY_OPT: DNP; CAD_APPROVED: Yes; FPLIST: RC0402_25,RC0402_HD,RC0402_X2,0402_CC; HEIGHT: 0.41mm; MFG_NAME01: VISHAY INTERTECHNOLOGY; MFG_PN01: CRCW04021K00JNED; ROHS: Yes; Tolerance: 5%
R123 R128 R132 R402 R413 = RES: RES MF 4.7K 1/16W 5% 0402; AGILE_PN: 470-75626; CAD_APPROVED: Yes; FPLIST: RC0402_25,RC0402_HD,0402_CC; HEIGHT: 0.41mm; MFG_NAME01: NIC COMPONENTS CORP; MFG_PN01: NRCL04J472TRF; ROHS: Yes; SIGNAL_MODEL: DEFAULT_RESISTOR_4700OHM_2_1; TOL: 5%; Tolerance: 5%
TP14-TP16 = T_POINT_R: TEST POINT PAD .035 SMT, no part to order; AGILE_PN: 510-75618; CAD_APPROVED: Yes; HEIGHT: 0.1MM; ROHS: Yes
U11 = KSZ8081RNB_32P: IC XCVR 10/100M EPHY 3.3V QFN32; AGILE_PN: 312-81089; CAD_APPROVED: Yes; HEIGHT: 0.9MM; MFG_NAME01: Micrel; MFG_PN01: KSZ8081RNBIA; ROHS: Yes
U12 = SRV05-4: DIODE TVS ARRAY 12A 5V 300W SOT23_S6; AGILE_PN: 480-75205; ASSY_OPT: DNP; CAD_APPROVED: Yes; HEIGHT: 1.45mm; MFG_NAME01: SEMTECH CORP; MFG_PN01: SRV05-4.TCT; ROHS: Yes
C175 = CAP_NP: CAP CER 10PF 16V 0.25PF C0G 0402; AGILE_PN: 150-75722; ASSY_OPT: DNP; CAD_APPROVED: Yes; FPLIST: CC0402_25,CC0402_HD,0402_CC; HEIGHT: 0.56MM; MFG_NAME01: SAMSUNG; MFG_PN01: CL05C100CO5NNNC; ROHS: Yes; Tolerance: 0.25PF; VOLTAGE: 16V
R176 R178 = RES: RES MF 100K 1/16W 5% 0402; AGILE_PN: 470-75597; ASSY_OPT: DNP; CAD_APPROVED: Yes; FPLIST: RC0402_25,RC0402_HD,0402_CC; HEIGHT: 0.40 MM; MFG_NAME01: VENKEL COMPANY; MFG_PN01: CR0402-16W-104JT; ROHS: Yes; Temp_Range: -55C to +155C; Tolerance: 5%
U14 = MT48LC16M16A2P_54P: IC MEM DRAM 16MX16 166MHZ SYNC 3.0-3.6V TSOPII54; AGILE_PN: 334-77751; CAD_APPROVED: Yes; HEIGHT: 1.2MM; MFG_NAME01: ISSI; ROHS: Yes; Temp_Range: -40C to +85C
C241 = CAP_NP: CAP CER 4.7UF 6.3V 20% X5R 0402; AGILE_PN: 150-78463; CAD_APPROVED: Yes; FPLIST: CC0402_25,CC0402_HD,0402_CC; HEIGHT: 0.65MM; MFG_NAME01: TDK; MFG_PN01: C1005X5R0J475M050BC; ROHS: Yes; TOL: 20%; Tolerance: 20%; VOLTAGE: 6.3V
C272 = CAP_NP: CAP CER 1000PF 50V 5% C0G 0402; AGILE_PN: 150-76334; CAD_APPROVED: Yes; FPLIST: CC0402_25,CC0402_HD,0402_CC; HEIGHT: 0.55MM; MFG_NAME01: MURATA; MFG_PN01: GRM1555C1H102JA01D; ROHS: Yes; Tolerance: 5%; VOLTAGE: 50V
C273 C274 = CAP_NP: CAP CER 27PF 50V 5% C0G 0402; AGILE_PN: 150-30109; CAD_APPROVED: Yes; FPLIST: CC0402_25,CC0402_HD,0402_CC; HEIGHT: .55mm; MFG_NAME01: KEMET; MFG_PN01: C0402C270J5GAC; ROHS: Yes; Tolerance: 5%; VOLTAGE: 50V
D20 D21 = LED: LED ULTRA BRIGHT RED SGL 30MA 0603; AGILE_PN: 370-75079; CAD_APPROVED: Yes; HEIGHT: 0.9MM; MFG_NAME01: LITE ON; MFG_PN01: LTST-C190KRKT; ROHS: Yes
J23 = USB_MINI_AB_RECEPTACLE: CON 5 USB MICRO_AB RA SKT SMT 0.65MM SP 110H AU; AGILE_PN: 211-80104; CAD_APPROVED: Yes; HEIGHT: 2.8MM; MFG_NAME01: ANYTRONIC CORPORATION LIMITED; MFG_PN01: 23971101#LCP-58RF; ROHS: Yes; Temp_Range: -55&#8451; to 105&#8451;
J34 = CONN_HDR_5X2: HDR 2X5 TH 50MIL CTR 172H AU 91L; AGILE_PN: 210-81466; CAD_APPROVED: Yes; HEIGHT: 4.38MM; MFG_NAME01: ANYTRONIC CORPORATION LIMITED; MFG_PN01: 0922S0205011N9T-31RF; ROHS: Yes; Temp_Range: -55DegC to +105DegC
J42 J44-J50 = CONN_HDR_2X1: HDR 1X2 TH 100MIL SP 339H AU 98L; AGILE_PN: 210-81490; CAD_APPROVED: Yes; HEIGHT: 8.59MM; MFG_NAME01: ANYTRONIC CORPORATION LIMITED; MFG_PN01: 0901S0202011N9T-31RF; ROHS: Yes; Temp_Range: -55°C to +105°C
J43 = CONN_HDR_3X1: HDR 1X3 TH 100MIL SP 338H AU 98L; AGILE_PN: 210-81491; CAD_APPROVED: Yes; HEIGHT: 8.59MM; MFG_NAME01: ANYTRONIC CORPORATION LIMITED; MFG_PN01: 0901S0203011N9T-31RF; ROHS: Yes; Temp_Range: -55°C to +105°C
L21-L23 = BEAD: IND FER BEAD 330OHM@100MHZ 1.7A 0603; AGILE_PN: 180-78156; CAD_APPROVED: Yes; FPLIST: ind_1608,0603_CC; HEIGHT: 0.95MM; MFG_NAME01: TDK; MFG_PN01: MPZ1608S331A; PART_TYPE: FERRITE\BEAD; ROHS: Yes; Tolerance: 25%
R212 = RES: RES MF 10K 1/16W 5% 0402; AGILE_PN: 470-75557; ASSY_OPT: DNP; CAD_APPROVED: Yes; FPLIST: RC0402_25,RC0402_HD,0402_CC; HEIGHT: 0.4 MM; MFG_NAME01: VISHAY INTERTECHNOLOGY; MFG_PN01: CRCW040210K0JNED; ROHS: Yes; Tolerance: 5%
R214 = RES: RES MF 15K  1/16W 1% 0402; AGILE_PN: 470-30965; CAD_APPROVED: Yes; FPLIST: RC0402_25,RC0402_HD,0402_CC; HEIGHT: 0.40 MM; MFG_NAME01: WALSIN TECHNOLOGY CORP.; MFG_PN01: WR04X1502FTL; ROHS: Yes; SIGNAL_MODEL: DEFAULT_RESISTOR_15000OHM_2_1; TOL: 1%; Tolerance: 1%
R351 = RES: RES MF 100K 1/16W 1% 0402; AGILE_PN: 470-76240; CAD_APPROVED: Yes; FPLIST: RC0402_25,RC0402_HD,0402_CC; HEIGHT: 0.4MM; MFG_NAME01: YAGEO AMERICA; MFG_PN01: RC0402FR-07100KL; ROHS: Yes; Tolerance: 1%
R377 = RES: RES MF 200K 1/10W 1% AEC-Q200 0402; AGILE_PN: 470-31093; CAD_APPROVED: Yes; FPLIST: RC0402_25,RC0402_HD,0402_CC; HEIGHT: 0.40 MM; MFG_NAME01: KOA SPEER; MFG_PN01: RK73H1ETTP2003F; ROHS: Yes; Temp_Range: -55C to +155C; Tolerance: 1%
R378 = RES: RES MF 464K 1/10W 1% AEC-Q200 0402; AGILE_PN: 470-31135; CAD_APPROVED: Yes; FPLIST: RC0402_25,RC0402_HD,0402_CC; HEIGHT: 0.40 MM; MFG_NAME01: KOA SPEER; MFG_PN01: RK73H1ETTP4643F; ROHS: Yes; Temp_Range: -55C to +155C; Tolerance: 1%
R379 R392 = RES: RES MF 270 OHM 1/16W 5% 0402; AGILE_PN: 470-81890; CAD_APPROVED: Yes; FPLIST: RC0402_25,RC0402_HD,0402_CC; HEIGHT: 0.4MM; MFG_NAME01: Yageo; MFG_PN01: RC0402JR-07270RL; ROHS: Yes; Temp_Range: -55C to +155C; Tolerance: 5%
R380-R382 R423 = RES: RES MF 12.0K 1/16W 1% 0402; AGILE_PN: 470-76083; CAD_APPROVED: Yes; FPLIST: RC0402_25,RC0402_HD,0402_CC; HEIGHT: 0.4 MM; MFG_NAME01: BOURNS; MFG_PN01: CR0402-FX-1202GLF; ROHS: Yes; Tolerance: 1%
R383 R418 R419 R422 = RES: RES MF 100K 1/16W 5% 0402; AGILE_PN: 470-75597; CAD_APPROVED: Yes; FPLIST: RC0402_25,RC0402_HD,0402_CC; HEIGHT: 0.40 MM; MFG_NAME01: VENKEL COMPANY; MFG_PN01: CR0402-16W-104JT; ROHS: Yes; TOL: 5%; Temp_Range: -55C to +155C; Tolerance: 5%
R387-R391 R414 = RES: RES MF 2.2K 1/16W 5% 0402; AGILE_PN: 470-76602; CAD_APPROVED: Yes; FPLIST: RC0402_25,RC0402_HD,0402_CC; HEIGHT: 0.4 MM; MFG_NAME01: YAGEO AMERICA; MFG_PN01: RC0402JR-072K2L; ROHS: Yes; TOL: 5%; Tolerance: 5%
R401 = RES: RES MF 180K 1/10W 1% AEC-Q200 0402; AGILE_PN: 470-31088; CAD_APPROVED: Yes; FPLIST: RC0402_25,RC0402_HD,0402_CC; HEIGHT: 0.40 MM; MFG_NAME01: KOA SPEER; MFG_PN01: RK73H1ETTP1803F; ROHS: Yes; SIGNAL_MODEL: DEFAULT_RESISTOR_180000OHM_2_1; TOL: 1%; Temp_Range: -55C to +155C; Tolerance: 1%
R416 R417 = RES: RES MF 100 OHM 1/16W 5% 0402; AGILE_PN: 470-82143; CAD_APPROVED: Yes; FPLIST: RC0402_25,RC0402_HD,RC0402_X2,0402_CC; HEIGHT: 0.45MM; MFG_NAME01: YAGEO AMERICA; MFG_PN01: RC0402JR-07100RL; ROHS: Yes; Temp_Range: -55°C to +155°C; Tolerance: 5%
SW9 = SW_PB_ESW: SW SPST MOM NO PB TACT 50mA 50V SMT; AGILE_PN: 510-77562; CAD_APPROVED: Yes; HEIGHT: 5MM; MFG_NAME01: E SWITCH; MFG_PN01: TL3301AF260QG/TR; ROHS: Yes
TP29 TP30 = TESTLOOP: TEST POINT PAD 30MIL DIA SMT, NO PART TO ORDER; AGILE_PN: 211-76642; CAD_APPROVED: Yes; HEIGHT: 0.1MM; MFG_NAME01: NOTACOMPONENT; MFG_PN01: NOTACOMPONENT; ROHS: Yes
U31 = NX5P3090UK_WLCSP12: IC USB PD TYPE C CURRENT LIMITED PWR SW 2.5-5.5V WLCSP12; AGILE_PN: 312-81574; CAD_APPROVED: Yes; HEIGHT: 0.565 MM; MFG_NAME01: NXP SEMICONDUCTORS; MFG_PN01: NX5P3090UK,012; ROHS: Yes
U39 = PRTR5V0U2X: IC USB ESD PROTECTION 8KV SOT143; AGILE_PN: 315-76725; CAD_APPROVED: Yes; HEIGHT: 1.1MM; MFG_NAME01: PHILIPS SEMICONDUCTOR; ROHS: Yes; Temp_Range: -40° C to +85° C
U40 = UM1750S-00_5P: IC VREG LDO ADJ 1-5V 350mA 2.5-6V SOT23-5; AGILE_PN: 315-80554; CAD_APPROVED: Yes; HEIGHT: 1.25MM; MFG_NAME01: Union Semiconductor, Inc; ROHS: Yes
U44 = NTSX2102GU8H_8P: IC DUAL SUPPLY XCVR 50 MBPS 5.5V XQFN8; AGILE_PN: 312-80763; CAD_APPROVED: Yes; HEIGHT: 0.5MM; MFG_NAME01: NXP Semiconductors; ROHS: Yes; VOLTAGE: 5.5V
U45 = NTB0102_8P: IC XCVR 2-BIT 1.65-3.6V/2.3-5.5V TSSOP8; AGILE_PN: 312-80889; CAD_APPROVED: Yes; HEIGHT: 1.1MM; MFG_NAME01: NXP SEMICONDUCTORS; MFG_PN01: NTS0102DP; ROHS: Yes
U46 U49 = 74LVCH1T45_6P: IC XCVR XLATING DUAL 3-STATE 1.2- 5.5V TSSOP6; AGILE_PN: 312-81277; CAD_APPROVED: Yes; HEIGHT: 1.1MM; MFG_NAME01: NEXPERIA; ROHS: Yes
U48 = 74LVC2T45DC_8P: IC TRANSLATING XCVR DUAL BIT/SUPPLY TS 1.2-5.5V VSSOP8; AGILE_PN: 312-81751; CAD_APPROVED: Yes; HEIGHT: 1MM; MFG_NAME01: NEXPERIA; ROHS: Yes; Temp_Range: -40°C to +125°C
U50 = LPC432_BGA_100P: IC MCU  CORTEX M4 CORE 512kB FLASH 2.4-3.6V BGA100; AGILE_PN: 344-02176; CAD_APPROVED: Yes; HEIGHT: 1.2MM; MFG_NAME01: NXP SEMICONDUCTORS; MFG_PN01: LPC4322JET100E; ROHS: Yes
Y5 = XTAL: XTAL 12MHZ RSN -- 18PF 30PPM SMT; AGILE_PN: 230-78082; CAD_APPROVED: Yes; HEIGHT: 3.3MM; MFG_NAME01: ABRACON CORP; MFG_PN01: ABLS2-12.000MHZ-D4Y-T; ROHS: Yes
R253-R264 = RES: RES MF 47K  1/16W 1% 0402; AGILE_PN: 470-31023; CAD_APPROVED: Yes; FPLIST: RC0402_25,RC0402_HD,0402_CC; HEIGHT: 0.40 MM; MFG_NAME01: YAGEO AMERICA; MFG_PN01: RC0402FR-0747KL; ROHS: Yes; Tolerance: 1%
SW8 = SW_DIP-4_SM: SW 4P SPST DIP 25MA 24V SMT; AGILE_PN: 510-77990; CAD_APPROVED: Yes; HEIGHT: 1.65 MM; MFG_NAME01: DIPTRONICS MANUFACTURING; MFG_PN01: DHN-04-V; ROHS: Yes

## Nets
5V_SDA_PSW: C241.1 R352.1 U31.C2(VBUS1) U31.D1(VBUS2) U31.D2(VBUS3)
5V_SYS: R82.1 ; also on sheet 3 4 6 7 15
GND: C91.2 C92.2 C93.2 C94.2 C95.2 C96.2 C97.2 C98.2 C99.2 C100.2 C101.1 C104.2 C105.2 C106.2 C107.1 C108.2 C109.2 C110.1 C116.2 C117.2 C118.2 C119.2 C120.1 C121.1 C124.2 C125.2 C126.2 C127.2 C128.2 C129.2 C130.2 C131.2 C132.2 C133.2 C134.2 C135.2 C136.2 C137.2 C144.2 C145.2 C146.2 C147.2 C148.2 C149.2 C150.2 C151.2 C175.2 C184.2 C185.2 C186.2 C241.2 C254.2 C255.2 C257.2 C258.2 C259.2 C260.2 C261.2 C262.2 C263.2 C264.2 C265.2 C266.2 C267.2 C268.2 C270.2 C272.2 C273.2 C274.2 C275.2 C276.2 C277.2 C278.2 D20.C(CATHODE) J11.1 J14.10(CHS_GND) J23.5(P5) J34.3(A2) J34.5(A3) J42.1 L10.1 L21.2 R86.1 R91.2 R103.1 R117.2 R120.2 R121.2 R122.2 R125.2 R126.2 R127.2 R131.2 R133.2 R134.2 R135.2 R137.2 R178.2 R214.2 R253.1 R254.1 R255.1 R256.1 R257.1 R258.1 R259.1 R260.1 R261.1 R262.1 R263.1 R264.1 R351.2 R377.2 R380.1 R387.1 R389.2 R391.2 R414.2 SW9.1(A1) SW9.2(A2) TVS2.1(A1) TVS3.1(A1) TVS4.1(A1) TVS5.1(A1) U10.9(DGND) U10.20(SPKGND2) U10.24(SPKGND1) U10.28(AGND) U10.33(GND_PADDLE) U11.1(GND) U11.33(PADDLE) U12.2(A2) U14.6(VSSQ1) U14.12(VSSQ2) U14.28(VSS1) U14.41(VSS2) U14.46(VSSQ3) U14.52(VSSQ4) U14.54(VSS3) U31.B3(GND1) U31.C3(GND2) U31.D3(GND3) U39.1(GND) U40.2(GND) U44.4(GND) U45.2(GND) U46.2(GND) U48.4(GND) U49.2(GND) U49.5(DIR) U50.C2(VSSA) U50.C8(VSS1) U50.D3(USB0_VSSA_TERM) U50.D4(VSS2) U50.D5(VSS3) U50.F2(USB0_VSSA_REF) U50.G8(VSS4) U50.J3(VSS5) U50.J6(VSS6) ; also on sheet 3 4 5 6 7 13 14 15
P3V3_SDA: C186.1 C255.1 C260.1 C262.1 C263.1 C264.1 C265.1 C266.1 C267.1 C270.1 J34.1(A1) L22.1 R213.1 R215.1 R378.1 R381.1 R382.1 R383.1 R388.2 R390.2 R394.1 R402.2 R413.1 R418.2 R423.1 U40.5(OUT) U44.1(VCCA) U45.3(VCCA) U46.1(VCCA) U48.1(VCCA) U49.1(VCCA) U50.B2(VDDA) U50.C5(VBAT) U50.D1(USB0_VDDA3V3_DRIVER) U50.D2(USB0_VDDA3V3) U50.F10(VDDIO1) U50.K5(VDDIO2)
P5V0_SDA_USB_CONN_VBUS: J23.1(P1) L23.1 U39.4(VCC)
P5V_SDA: C184.1 C185.1 C257.1 C259.1 L23.2 R212.1 R353.1 R379.1 U31.B1(VINT1) U31.B2(VINT2) U31.C1(VINT3) U40.1(IN) U40.3(~{SHDN})
P5V_SDA_S: R352.2 R353.2 ; also on sheet 3
AUD_INT: R83.1 R84.1 ; also on sheet 5
BOOT0_LED: R388.1 R392.1 U50.K2(P1_1/GPIO0[8]/CTOUT_7/EMC_A6/SGPIO8/SSP0_MISO/EMC_D13)
BOOT1: R389.1 U50.K1(P1_2/GPIO0[9]/CTOUT_6/EMC_A7/SGPIO9/SSP0_MOSI/EMC_D14)
BOOT2: R390.1 U50.C6(P2_8/SGPIO15/CTOUT_0/U3_DIR/EMC_A8/GPIO5[7])
BOOT3: R391.1 U50.B10(P2_9/GPIO1[10]/CTOUT_3/U3_BAUD/EMC_A0)
BOOT_FLASH: J42.2 U50.C10(P2_7/GPIO0[7]/CTOUT_1/U3_UCLK/EMC_A9/T3_MAT3)
DCDC_3V3: C134.1 C268.1 C275.1 C276.1 C277.1 C278.1 J14.1(LED_Y1) J14.12(LED_G12) L9.1 L13.1 R80.1 R108.1 R109.1 R110.1 R111.1 R113.1 R114.1 R115.1 R118.2 R119.2 R123.2 R124.2 R128.2 R129.2 R130.2 R132.2 R136.2 R393.1 R401.1 R411.1 R412.1 R419.2 R422.2 U11.17(VDDIO) U44.8(VCCB) U45.7(VCCB) U46.6(VCCB) U48.8(VCCB) U49.6(VCCB) ; also on sheet 4 5 6 7 13 14 15
ENET_B-CAST-OFF: R136.1 TP14.1(TP) U11.19(REF_CLK/B-CAST_OFF)
ENET_CONFIG0: R125.1 R128.1 U11.28(CONFIG0)
ENET_CONFIG1: R126.1 R129.1 U11.29(CONFIG1)
ENET_CRS_DV: R127.1 R130.1 U11.18(CRS_DV/CONFIG2) ; also on sheet 5 15
ENET_INT: R115.2 R137.1 U11.21(INTRP/~{NAND_TREE}) ; also on sheet 5 15
ENET_LED0/NWAYEN: J14.2(LED_Y2) R133.1 U11.30(LED0/NWAYEN)
ENET_LED1/SPEED: J14.11(LED_G11) R134.1 U11.31(LED1/SPEED)
ENET_MDC: R114.2 U11.12(MDC) ; also on sheet 5
ENET_MDIO: R113.2 U11.11(MDIO) ; also on sheet 5
ENET_PHYAD0: R119.1 R122.1 U11.13(PHYAD0)
ENET_PHYAD1: R120.1 R123.1 U11.14(PHYAD1)
ENET_RST: J50.2 R116.1 ; also on sheet 5 15
ENET_RXD0: R135.1 U11.16(RXD0/DUPLEX) ; also on sheet 5 15
ENET_RXD1: R121.1 R124.1 U11.15(RXD1/PHYAD2) ; also on sheet 5 15
ENET_RXER: R131.1 R132.1 U11.20(RXER/ISO) ; also on sheet 5 15
ENET_RXM: C133.1 J14.8(RD-) R111.2 U11.4(RXM) U12.3(A3)
ENET_RXP: C132.1 J14.7(RD+) R110.2 U11.5(RXP) U12.1(A1)
ENET_TX_CLK: TP16.1(TP) U11.9(XI) ; also on sheet 5
ENET_TXD0: TP15.1(TP) U11.24(TXD0) ; also on sheet 5 15
ENET_TXD1: U11.25(TXD1) ; also on sheet 5 15
ENET_TXEN: U11.23(TXEN) ; also on sheet 5 15
ENET_TXM: C131.1 J14.4(TD-) R109.2 U11.6(TXM) U12.4(A4)
ENET_TXP: C130.1 J14.3(TD+) R108.2 U11.7(TXP) U12.6(A6)
GPIO_AD_B0_06: J46.2 R393.2 ; also on sheet 5 15
GPIO_AD_B0_07: J45.2 R411.2 ; also on sheet 5 15
GPIO_AD_B1_14: R92.2 U10.17(SCLK) ; also on sheet 5 15
GPIO_AD_B1_15: R93.2 U10.18(SDIN) ; also on sheet 5 15
GPIO_EMC_16: R254.2 R299.2 SW8.4(A4) U14.23(A0)
GPIO_EMC_17: R253.2 R300.2 SW8.3(A3) U14.24(A1)
GPIO_EMC_18: R264.2 R301.2 SW8.1(A1) U14.25(A2)
GPIO_EMC_19: R263.2 R302.2 U14.26(A3)
GPIO_EMC_20: R262.2 R303.2 U14.29(A4)
GPIO_EMC_21: R261.2 R288.2 U14.30(A5)
GPIO_EMC_22: R260.2 R271.2 R289.2 U14.31(A6)
GPIO_EMC_23: R259.2 R290.2 SW8.2(A2) U14.32(A7)
GPIO_EMC_24: R258.2 R295.2 R315.2 U14.33(A8)
GPIO_EMC_25: R257.2 R294.2 R314.2 U14.34(A9)
GPIO_EMC_26: R256.2 R270.2 R296.2 U14.35(A11)
GPIO_EMC_27: R255.2 R269.2 R298.2 U14.36(A12)
HP_JD: J11.5 R81.2 R84.2 TVS3.2(A2) U10.7(RINPUT3/JD3)
HP_L: C102.1 U10.31(HP_L)
HP_MIC1N: C110.2 C112.1 U10.4(LINPUT1)
HP_MIC1P: C115.1 C116.1 U10.2(LINPUT3/JD2)
HP_R: C103.1 U10.29(HP_R)
JTAG_RESET: J44.2 U50.D10(P2_5/SGPIO14/CTIN_2/USB1_VBUS/ADCTRIG1/GPIO5[5]/T3_MAT2/USB0_IND0)
JTAG_TCK: J48.2 ; also on sheet 5 15
JTAG_TDI: J49.2 ; also on sheet 4 5 15
JTAG_TDI_L: U48.3(2A) U50.J10(P1_18/GPIO0[13]/U2_DIR/ENET_TXD0/T0_MAT3/CAN1_RD/SGPIO12/EMC_D10)
JTAG_TDI_TGTMCU_BUF: J49.1 R417.2
JTAG_TDO_TGTMCU_BUF: J50.1 R422.1 U49.4(B)
JTAG_TMS: J47.2 ; also on sheet 5 15
MAIN_MIC2N: C114.2 C119.1 U10.5(RINPUT1)
MAIN_MIC2P: C107.2 C111.2 U10.6(RINPUT2)
MICBIAS: C98.1 R94.1 R95.1 U10.1(MICBIAS)
POR_B: D21.C(CATHODE) J43.3 R401.2 R410.2 U44.7(B1) ; also on sheet 4 15
POWER_EN: R216.1 U50.F7(P3_1/I2S0_TX_WS/I2S0_RX_WS/CAN0_RD/USB1_IND1/GPIO5[8]/LCD_VD15)
SAI1_MCLK: R90.1 ; also on sheet 5
SAI1_RXD: R88.1 ; also on sheet 5
SAI1_TX_BCLK: R87.1 ; also on sheet 5
SAI1_TX_SYNC: R85.1 ; also on sheet 5
SAI1_TXD: R89.1 ; also on sheet 5
SDA_JTAG_TCLK: J34.4(B2) U50.H2(TCK/SWDCLK)
SDA_JTAG_TDI: J34.8(B4) U50.G3(TDI)
SDA_JTAG_TDO: J34.6(B3) U50.H3(TDO/SWO)
SDA_JTAG_TMS: J34.2(B1) R213.2 U50.C4(TMS/SWDIO)
SDA_RST: J34.10(B5) R423.2 U50.B4(~{TRST})
SDA_RST_LED: D21.A(ANODE) R412.2
SDA_RST_TGTMCU_J_B: J44.1 R400.1 R410.1
SDA_USB_CONN_DM: J23.2(P2) R375.1 U39.2(I/O1)
SDA_USB_CONN_DP: J23.3(P3) R376.1 U39.3(I/O2)
SDA_USB_DM: R375.2 U50.E2(USB0_DM)
SDA_USB_DP: R376.2 U50.E1(USB0_DP)
SDA_USBSHIELD: J23.S1(SHLD1) J23.S2(SHLD2) J23.S3(SHLD3) J23.S4(SHLD4) L21.1
SDRAM_3V3: C144.1 C145.1 C146.1 C147.1 C148.1 C149.1 C150.1 C151.1 L13.2 R176.1 R265.1 R266.1 R267.1 R268.1 R269.1 R270.1 R271.1 R314.1 R315.1 U14.1(VDD1) U14.3(VDDQ1) U14.9(VDDQ2) U14.14(VDD2) U14.27(VDD3) U14.43(VDDQ3) U14.49(VDDQ4)
SEMC_A0: R299.1 ; also on sheet 5
SEMC_A1: R300.1 ; also on sheet 5
SEMC_A2: R301.1 ; also on sheet 5
SEMC_A3: R302.1 ; also on sheet 5
SEMC_A4: R303.1 ; also on sheet 5
SEMC_A5: R288.1 ; also on sheet 5
SEMC_A6: R289.1 ; also on sheet 5
SEMC_A7: R290.1 ; also on sheet 5
SEMC_A8: R295.1 ; also on sheet 5
SEMC_A9: R294.1 ; also on sheet 5
SEMC_A10: R297.1 ; also on sheet 5
SEMC_A11: R296.1 ; also on sheet 5
SEMC_A12: R298.1 ; also on sheet 5
SEMC_BA0: R291.1 ; also on sheet 5
SEMC_BA1: R293.1 ; also on sheet 5
SEMC_CAS: R307.1 ; also on sheet 5
SEMC_CKE: R306.1 ; also on sheet 5
SEMC_CLK: R177.1 ; also on sheet 5
SEMC_CS0: R311.1 ; also on sheet 5
SEMC_D0: R272.2 ; also on sheet 5
SEMC_D1: R273.2 ; also on sheet 5
SEMC_D2: R274.2 ; also on sheet 5
SEMC_D3: R275.2 ; also on sheet 5
SEMC_D4: R276.2 ; also on sheet 5
SEMC_D5: R277.2 ; also on sheet 5
SEMC_D6: R278.2 ; also on sheet 5
SEMC_D7: R279.2 ; also on sheet 5
SEMC_D8: R283.2 ; also on sheet 5
SEMC_D9: R284.2 ; also on sheet 5
SEMC_D10: R285.2 ; also on sheet 5
SEMC_D11: R286.2 ; also on sheet 5
SEMC_D12: R287.2 ; also on sheet 5
SEMC_D13: R280.2 ; also on sheet 5
SEMC_D14: R281.2 ; also on sheet 5
SEMC_D15: R282.2 ; also on sheet 5
SEMC_DM0: R310.1 ; also on sheet 5
SEMC_DM1: R309.1 ; also on sheet 5
SEMC_RAS: R308.1 ; also on sheet 5
SEMC_WE: R304.1 ; also on sheet 5
SPK_LN: R105.1 U10.23(SPK_LN)
SPK_LP: R107.1 U10.25(SPK_LP)
SPK_RN: R104.1 U10.19(SPK_RN)
SPK_RP: R106.1 U10.22(SPK_RP)
SW1_RST_B: C272.1 J43.2 SW9.3(B1) SW9.4(B2)
SWD_CLK_TGTMCU_BUF: J48.1 R416.2
SWD_DIO_TGTMCU_BUF: J47.1 R419.1 U46.4(B)
TC_SDA_USB_ID: J23.4(P4) U50.F1(USB0_ID)
TCK_SWCLK: U48.2(1A) U50.H10(P1_17/GPIO0[12]/U2_UCLK/ENET_MDIO/T0_CAP3/CAN1_TD/SGPIO11)
TDO_SWO: U49.3(A) U50.J8(P1_14/GPIO1[7]/U1_RXD/EMC_D7/T0_MAT2/SGPIO10)
TMS_SWDIO: U46.3(A) U50.K4(P1_6/GPIO1[9]/CTIN_5/~{EMC_WE}/~{EMC_BLS0}/SGPIO14/SD_CMD)
TMS_SWDIO_TXEN: R414.1 U46.5(DIR) U50.J4(P1_5/GPIO1[8]/CTOUT_10/~{EMC_CS0}/USB0_PWR_FAULT/SSP1_SSEL/SGPIO15/SD_POW)
TP_2102_A: TP29.1(Pin1) U44.3(A2)
TP_2102_B: TP30.1(Pin1) U44.6(B2)
UART1_RX_TGTMCU_BUF: J45.1 U45.8(B1)
UART1_TX_TGTMCU_BUF: J46.1 U45.1(B2)
UART_RXD_ISP: U45.5(A1) U50.G10(P2_0/SGPIO4/U0_TXD/EMC_A13/USB0_PPWR/GPIO5[0]/T3_CAP0/ENET_MDC)
UART_TXD_ISP: U45.4(A2) U50.G7(P2_1/SGPIO5/U0_RXD/EMC_A12/USB0_PWR_FAULT/GPIO5[1]/T3_CAP1)
VAUD_3V3: C91.1 C92.1 C93.1 C94.1 R80.2 R81.1 R92.1 R93.1 U10.8(DCVDD) U10.10(DBVDD) U10.32(AVDD)
VTRG_FAULT_B: R215.2 U31.A2(~{FAULT}) U50.A8(P3_0/I2S0_RX_SCK/I2S0_RX_MCLK/I2S0_TX_SCK/I2S0_TX_MCLK/SSP0_SCK)
N99815013: C126.1 C127.1 L9.2 U11.3(VDDA_3.3)
N99815680: C128.1 C129.1 U11.2(VDD_1.2)
N99815919: C135.1 J14.6(CT1)
N99815924: C136.1 J14.5(CT2)
N99816488: J14.13(SH1) J14.14(SH2) L10.2
N99820323: R117.1 U11.10(REXT)
N99825452: C95.1 C96.1 C97.1 C99.1 R82.2 U10.21(SPKVDD2) U10.26(SPKVDD1)
N99827287: C100.1 U10.27(VMID)
N99827729: R83.2 U10.15(ADCLRC/GPIO1)
N99827749: R85.2 U10.13(DACLRC)
N99827769: R87.2 U10.12(BCLK)
N99827789: R88.2 U10.16(ADCDAT)
N99827809: R89.2 U10.14(DACDAT)
N99827829: R90.2 U10.11(MCLK)
N99827958: C120.2 C122.1 J12.2 R104.2
N99827962: C122.2 C124.1 J12.1 R106.2
N99828318: C121.2 C123.1 J13.2 R105.2
N99828322: C123.2 C125.1 J13.1 R107.2
N99903207: C102.2 L6.1 R86.2
N99903209: C103.2 L7.1 R91.1
N99903219: C104.1 J11.3 L7.2 TVS4.2(A2)
N99903223: C101.2 J11.2 L6.2 TVS2.2(A2)
N99903738: J11.4 L8.2 TVS5.2(A2)
N99904959: C112.2 R97.2 R100.1
N99904961: C115.2 C117.1 C118.1 L8.1 R100.2
N99904975: C108.1 C109.1 R94.2 R97.1
N99907436: C113.2 R102.2 R103.2
N99907447: C114.1 R99.2 R101.2 R102.1
N99907449: C111.1 R96.2 R98.2 R99.1
N99907458: C105.1 C106.1 C113.1 R95.2 R96.1
N99907542: P1.1(Out) R98.1
N99907546: P1.2(GND) R101.1
N100226419: R266.2 SW8.6(B3)
N100226426: R267.2 SW8.7(B2)
N100226433: R268.2 SW8.8(B1)
N101050998: C137.1 R116.2 R118.1 U11.32(~{RST})
N101219622: C175.1 R177.2 U14.38(CLK)
N101507443: R272.1 U14.2(DQ0)
N101507450: R273.1 U14.4(DQ1)
N101507457: R274.1 U14.5(DQ2)
N101507470: R275.1 U14.7(DQ3)
N101507472: R276.1 U14.8(DQ4)
N101507474: R277.1 U14.10(DQ5)
N101507491: R278.1 U14.11(DQ6)
N101507493: R279.1 U14.13(DQ7)
N101507495: R283.1 U14.42(DQ8)
N101507512: R284.1 U14.44(DQ9)
N101507514: R285.1 U14.45(DQ10)
N101507516: R286.1 U14.47(DQ11)
N101507533: R287.1 U14.48(DQ12)
N101507535: R280.1 U14.50(DQ13)
N101507537: R281.1 U14.51(DQ14)
N101507548: R282.1 U14.53(DQ15)
N101509422: R297.2 U14.22(A10)
N101509590: R291.2 U14.20(BA0)
N101509597: R293.2 U14.21(BA1)
N101509855: R178.1 R306.2 U14.37(CKE)
N101509857: R309.2 U14.39(DQMH)
N101509859: R310.2 U14.15(DQML)
N101509861: R308.2 U14.18(~{RAS})
N101509863: R304.2 U14.16(~{WE})
N101510168: R307.2 U14.17(~{CAS})
N101511316: R176.2 R311.2 U14.19(~{CS})
N101583028: R265.2 SW8.5(B4)
N101646424: D20.A(ANODE) R392.2
N101646485: R387.2 U50.C9(P6_11/GPIO3[7]/EMC_CKEOUT0/T2_MAT3)
N101647261: R351.1 U31.A3(ILIM)
N101647280: R212.2 R214.1 R216.2 U31.A1(EN)
N101652174: J43.1 R394.2 R400.2 U44.2(A1)
N101652379: R402.1 U44.5(OE)
N101652682: R413.2 U45.6(OE)
N101652838: R416.1 U48.7(1B)
N101652851: R417.1 U48.6(2B)
N101652913: R418.1 U48.5(DIR)
N101655535: R377.1 R378.2 U40.4(FB)
N101655576: R379.2 U50.E3(USB0_VBUS)
N101655591: R380.2 U50.F3(USB0_RREF)
N101655607: C254.1 C258.1 C261.1 L22.2 U50.E4(VDDREG1) U50.E5(VDDREG2) U50.F4(VDDREG3)
N101655735: R381.2 U50.A6(DBGEN)
N101655737: R382.2 U50.B6(~{RESET})
N101655752: R383.2 U50.A4(WAKEUP0)
N101655907: C274.1 U50.B1(XTAL1) Y5.1
N101656203: C273.1 U50.C1(XTAL2) Y5.2

Not connected (* = marked no-connect by the designer): J11 6*; J14 9(NC)*; J34 7(A4)* 9(A5)*; U10 3(LINPUT2)* 30(OUT3)*; U11 8(XO)* 22(NC1)* 26(NC2)* 27(NC3)*; U12 5(A5)*; U14 40(NC)*; U50 A1(ADC0_1/ADC1_1)* A2(ADC0_0/ADC1_0/DAC)* A3(ADC0_3/ADC1_3)* A5(RTCX1)* A7(P3_3/SPI_SCK/SSP0_SCK/SPIFI_SCK/CGU_OUT1/I2S0_TX_MCLK/I2S1_TX_SCK)* A9(P2_11/GPIO1[11]/CTOUT_5/U2_RXD/EMC_A2)* A10(P2_13/GPIO1[13]/CTIN_4/EMC_A4/U2_DIR)* B3(ADC0_2/ADC1_2)* B5(RTCX2)* B7(P3_5/GPIO1[15]/SPIFI_SIO2/U1_RXD/I2S0_TX_SDA/I2S1_RX_WS/LCD_VD12)* B8(P3_4/GPIO1[14]/SPIFI_SIO3/U1_TXD/I2S0_TX_WS/I2S1_RX_SDA/LCD_VD13)* B9(P2_12/GPIO1[12]/CTOUT_4/EMC_A3/U2_UCLK)* C3(RTC_ALARM)* C7(P3_6/GPIO0[6]/SPI_MISO/SSP0_SSEL/SPIFI_MISO/SSP0_MISO)* D6(I2C0_SCL)* D7(P3_7/SPI_MOSI/SSP0_MISO/SPIFI_MOSI/GPIO5[10]/SSP0_MOSI)* D8(P2_3/SGPIO12/I2C1_SDA/U3_TXD/CTIN_1/GPIO5[3]/T3_MAT0/USB0_PPWR)* D9(P2_4/SGPIO13/I2C1_SCL/U3_RXD/CTIN_0/GPIO5[4]/T3_MAT1/USB0_PWR_FAULT)* E6(I2C0_SDA)* E7(P3_8/SPI_SSEL/SSP0_MOSI/SPIFI_CS/GPIO5[11]/SSP0_SSEL)* E8(P2_10/GPIO0[14]/CTOUT_2/U2_TXD/EMC_A1)* E9(USB1_DP)* E10(USB1_DM)* F5(P2_2/SGPIO6/U0_UCLK/EMC_A11/USB0_IND1/GPIO5[2]/CTIN_6/T3_CAP2/~{EMC_CS1})* F6(P6_4/GPIO3[3]/CTIN_6/U0_TXD/~{EMC_CAS})* F8(P6_9/GPIO3[5]/~{EMC_DYCS0}/T2_MAT2)* F9(P6_5/GPIO3[4]/CTOUT_6/U0_RXD/~{EMC_RAS})* G1(P0_1/GPIO0[1]/SSP1_MOSI/ENET_COL/SGPIO1/ENET_TX_EN/I2S1_TX_SDA)* G2(P0_0/GPIO0[0]/SSP1_MISO/ENET_RXD1/SGPIO0/I2S0_TX_WS/I2S1_TX_WS)* G4(P1_7/GPIO1[0]/U1_DSR/CTOUT_13/EMC_D0/USB0_PPWR)* G5(P6_1/GPIO3[0]/~{EMC_DYCS1}/U0_UCLK/I2S0_RX_WS/T2_CAP0)* G6(P3_2/I2S0_TX_SDA/I2S0_RX_SDA/CAN0_TD/USB1_IND0/GPIO5[9]/LCD_VD14)* G9(P2_6/SGPIO7/U0_DIR/EMC_A10/USB0_IND0/GPIO5[6]/CTIN_7/T3_CAP3/~{EMC_BLS1}) H1(P1_0/GPIO0[4]/CTIN_3/EMC_A5/SSP0_SSEL/SGPIO7/EMC_D12)* H4(PF_4/SSP1_SCK/GP_CLKIN/TRACECLK/I2S0_TX_MCLK/I2S0_RX_SCK)* H5(P1_8/GPIO1[1]/U1_DTR/CTOUT_12/EMC_D1/SD_VOLT0)* H6(P1_10/GPIO1[3]/U1_RI/CTOUT_14/EMC_D3/SD_DAT1)* H7(P6_0/I2S0_RX_MCLK/I2S0_RX_SCK)* H8(P1_13/GPIO1[6]/U1_TXD/EMC_D6/T0_CAP0/SGPIO9/SD_CD)* H9(P1_16/GPIO0[3]/U2_RXD/SGPIO3/ENET_CRS/T0_MAT0/EMC_D9/ENET_RX_DV)* J1(P1_3/GPIO0[10]/CTOUT_8/SGPIO10/~{EMC_OE}/USB0_IND1/SSP1_MISO/SD_RST)* J2(P1_4/GPIO0[11]/CTOUT_9/SGPIO11/~{EMC_BLS0}/USB0_IND0/SSP1_MOSI/EMC_D15/SD_VOLT1)* J5(P1_9/GPIO1[2]/U1_RTS/CTOUT_11/EMC_D2/SD_DAT0)* J7(P1_11/GPIO1[4]/U1_CTS/CTOUT_15/EMC_D4/SD_DAT2)* J9(P6_2/GPIO3[1]/EMC_CKEOUT1/U0_DIR/I2S0_RX_SDA/T2_CAP1)* K3(CLK0/EMC_CLK0/CLKOUT/SD_CLK/EMC_CLK01/SSP1_SCK/ENET_TX_CLK/ENET_REF_CLK)* K6(CLK2/EMC_CLK3/CLKOUT/SD_CLK/EMC_CLK23/I2S0_TX_MCLK/I2S1_RX_SCK)* K7(P1_12/GPIO1[5]/U1_DCD/EMC_D5/T0_CAP1/SGPIO8/SD_DAT3)* K8(P1_15/GPIO0[2]/U2_TXD/SGPIO2/ENET_RXD0/T0_MAT1/EMC_D8)* K9(P1_19/ENET_TX_CLK/ENET_REF_CLK/SSP1_SCK/CLKOUT/I2S0_RX_MCLK/I2S1_TX_SCK)* K10(P1_20/GPIO0[15]/SSP1_SSEL/ENET_TXD1/T0_CAP2/SGPIO13/EMC_D11)*

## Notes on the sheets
sheet 8
- OFF, SLEEP MODE
- MAX 50 mA @3.3V
- DCVDD
  DBVDD
  AVDD
  SPKVDD
- 1.71V - 3.6V
  1.71V - 3.6V
  2.70V - 3.6V
  2.70V - 5.5V
- HP JACK
- MAX 0.5A @5V
- # HP_DET:
      LOW : REMOVE
      HIGH : PLUG
- Main Board MIC
- HP MIC
- Speaker
sheet 9
- MAX 50 mA @3.3V
- Differential 100ohm
  Difference tolerance 100mil
- Differential 100ohm
  Difference tolerance 100mil
- Ethernet Circuit
- ESD PROTECTION
- # CFG
- Description
- # CFG
- Description
- PHYAD[2:0]
- PHY ADDR
- DUPLEX mode
- Ipu/O
- 00-XXX (00010 DEFAULT)
- DUPLEX
- Pull-up  (default) = Half Duplex
  Pull-down = Full Duplex
- Ipd/O
- Ipd/O
- IF MODE
- CONFIG[2:0]
- 001 RMII
  101 RMII Back-to-Back
  xxx Reserved-not used
- Nway Auto-Negotiation
- NWAYEN
- Pull-up  (default) = Enable
  Pull-down = Disable
- Ipd/O
- Ipd/O
- Ipd/O
- ISOLATE mode
- Broadcast Off - for PHY Address 0
- Ipd/O
- ISO
- Pull-up =  Enable
  Pull-down (default) = Disable
- B_CAST_OFF
- Pull-up = PHY Address 0 set as unique PHY addr
  Pull-down (default) = PHY Address 0 set as broadcast PHY addr
- Ipu/O
- Ipu/O
- Ipu/O
- Ipd/O
- SPEED mode
- NAND Tree Mode
- Ipu/Opu
- SPEED
- Pull-up  (default) =  100Mbps
  Pull-down = 10Mbps
- NAND_TREE#
- Pull-up  (default) = Disable
  Pull-down =  Enable
sheet 10
- SDRAM
- MAX 150 mA @3.3V
- close to MCU pin
sheet 11
- Freelink Interface
- Vfb=1V
- Short (JP42) to force
  DFU Boot Mode
- JTAG CONNECTOR
- RESET
- 1-2: Default.
  2-3: Reset signal direct to the MCU,
  to use when OpenSDA is not powered.
- RST Push Button
  Bypass
- TARGET MCU
  INTERFACE
  SIGNALS
- RST_TGTMCU_B
- PWR SWITCH
- (To enable 5V from
   USB connector)
- UART1_RX_TGTMCU
- Isolation
  Jumpers
- MAX 500 mA @5V
- UART1_TX_TGTMCU
- SWD_DIO_TGTMCU
- SWD_CLK_TGTMCU
- JTAG_TDI_TGTMCU
- JTAG_TDO_TGTMCU
sheet 12
- FUSE MAP
- 0/1
- 0/1
- 0/1
- 0/1
- 0/1
- 0/1
- 0/1
- 0/1
- 0/1
- 0/1
- TYPE
- BOOT_CFG[9]
- BOOT_CFG[8]
- BOOT_CFG[7]
- BOOT_CFG[6]
- BOOT_CFG[5]
- BOOT_CFG[4]
- BOOT_CFG[3]
- BOOT_CFG[2]
- BOOT_CFG[1]
- BOOT_CFG[0]
- FLASH_TYPE:
  000-Device supports 3B read by default
  001-Device supports 4B read by default
  010-HyperFlash 1V8
  011-HyperFlash 3V3
  100-MXIC Octal DDR
  101 - Micron Octal DDR
  111 - QSPI device supports 3B read by default
   (on secondary pinmux option)
- HOLD TIME:
  00 - 500us
  01 - 1ms
  10 - 3ms
  11 - 10ms
- EncryptedXIP
  0 - Disabled
  1- Enabled
- FlexSPI1 - Serial NOR
- 0
- 0
- 0
- 0
- SD/SDXC Speed:
  00 - Normal/SDR12
  01 - High/SDR25
  10 - SDR50
  11 - SDR104
- SD Power
  Cycle Enable:
  '0' - No power
  cycle
  '1' - Enabled via
  USDHC_RST pad
- SD Loopback
  Clock Source
  Sel: (for SDR50
  and SDR104 only)
  '0' - through SD pad
  '1' -  direct
- Bus Width:
  0 - 1-bit
  1 - 4-bit
- Port Select:
  0 - eSDHC1
  1 - eSDHC2
- Fast Boot:
  0 - Regular
  1 - Fast Boot
- SD
- 0
- 0
- 1
- "CS_INTERVAL:
  CS de-asserted
   interval between two commands
  0 ¨C 100ns
  1 ¨C 200ns
  2 ¨C 400ns
  3 ¨C 50ns"
- BOOT_SEARCH_STRIDE:
  Search Stride for FCB and DBBT
   (in terms of pages)
  0 - 64
  1 - 128
  2 - 256
  3 - 32
- SPI NAND HOLD TIME
  00 - 0 us
  01 - 500us
  10 - 1ms
  11 - 3ms
- BOOT_SEARCH
  _COUNT:
  0 - 1
  1 - 2
- COL_ADDRESS
  _WIDTH:
  0 ¨C 12bits
  1 ¨C 13bits
- 1
- 1
- FlexSPI1 - Serial NAND
